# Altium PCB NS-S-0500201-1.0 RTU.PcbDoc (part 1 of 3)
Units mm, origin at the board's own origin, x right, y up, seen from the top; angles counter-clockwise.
Board outline 170 x 90 mm, 6 copper layers (TOP, L2_GND, L3_SIG, L4_VCC, L5_GND, BOT), stack 1.4 mm thick; 260 components, 230 nets, 1133 pads, 705 vias.
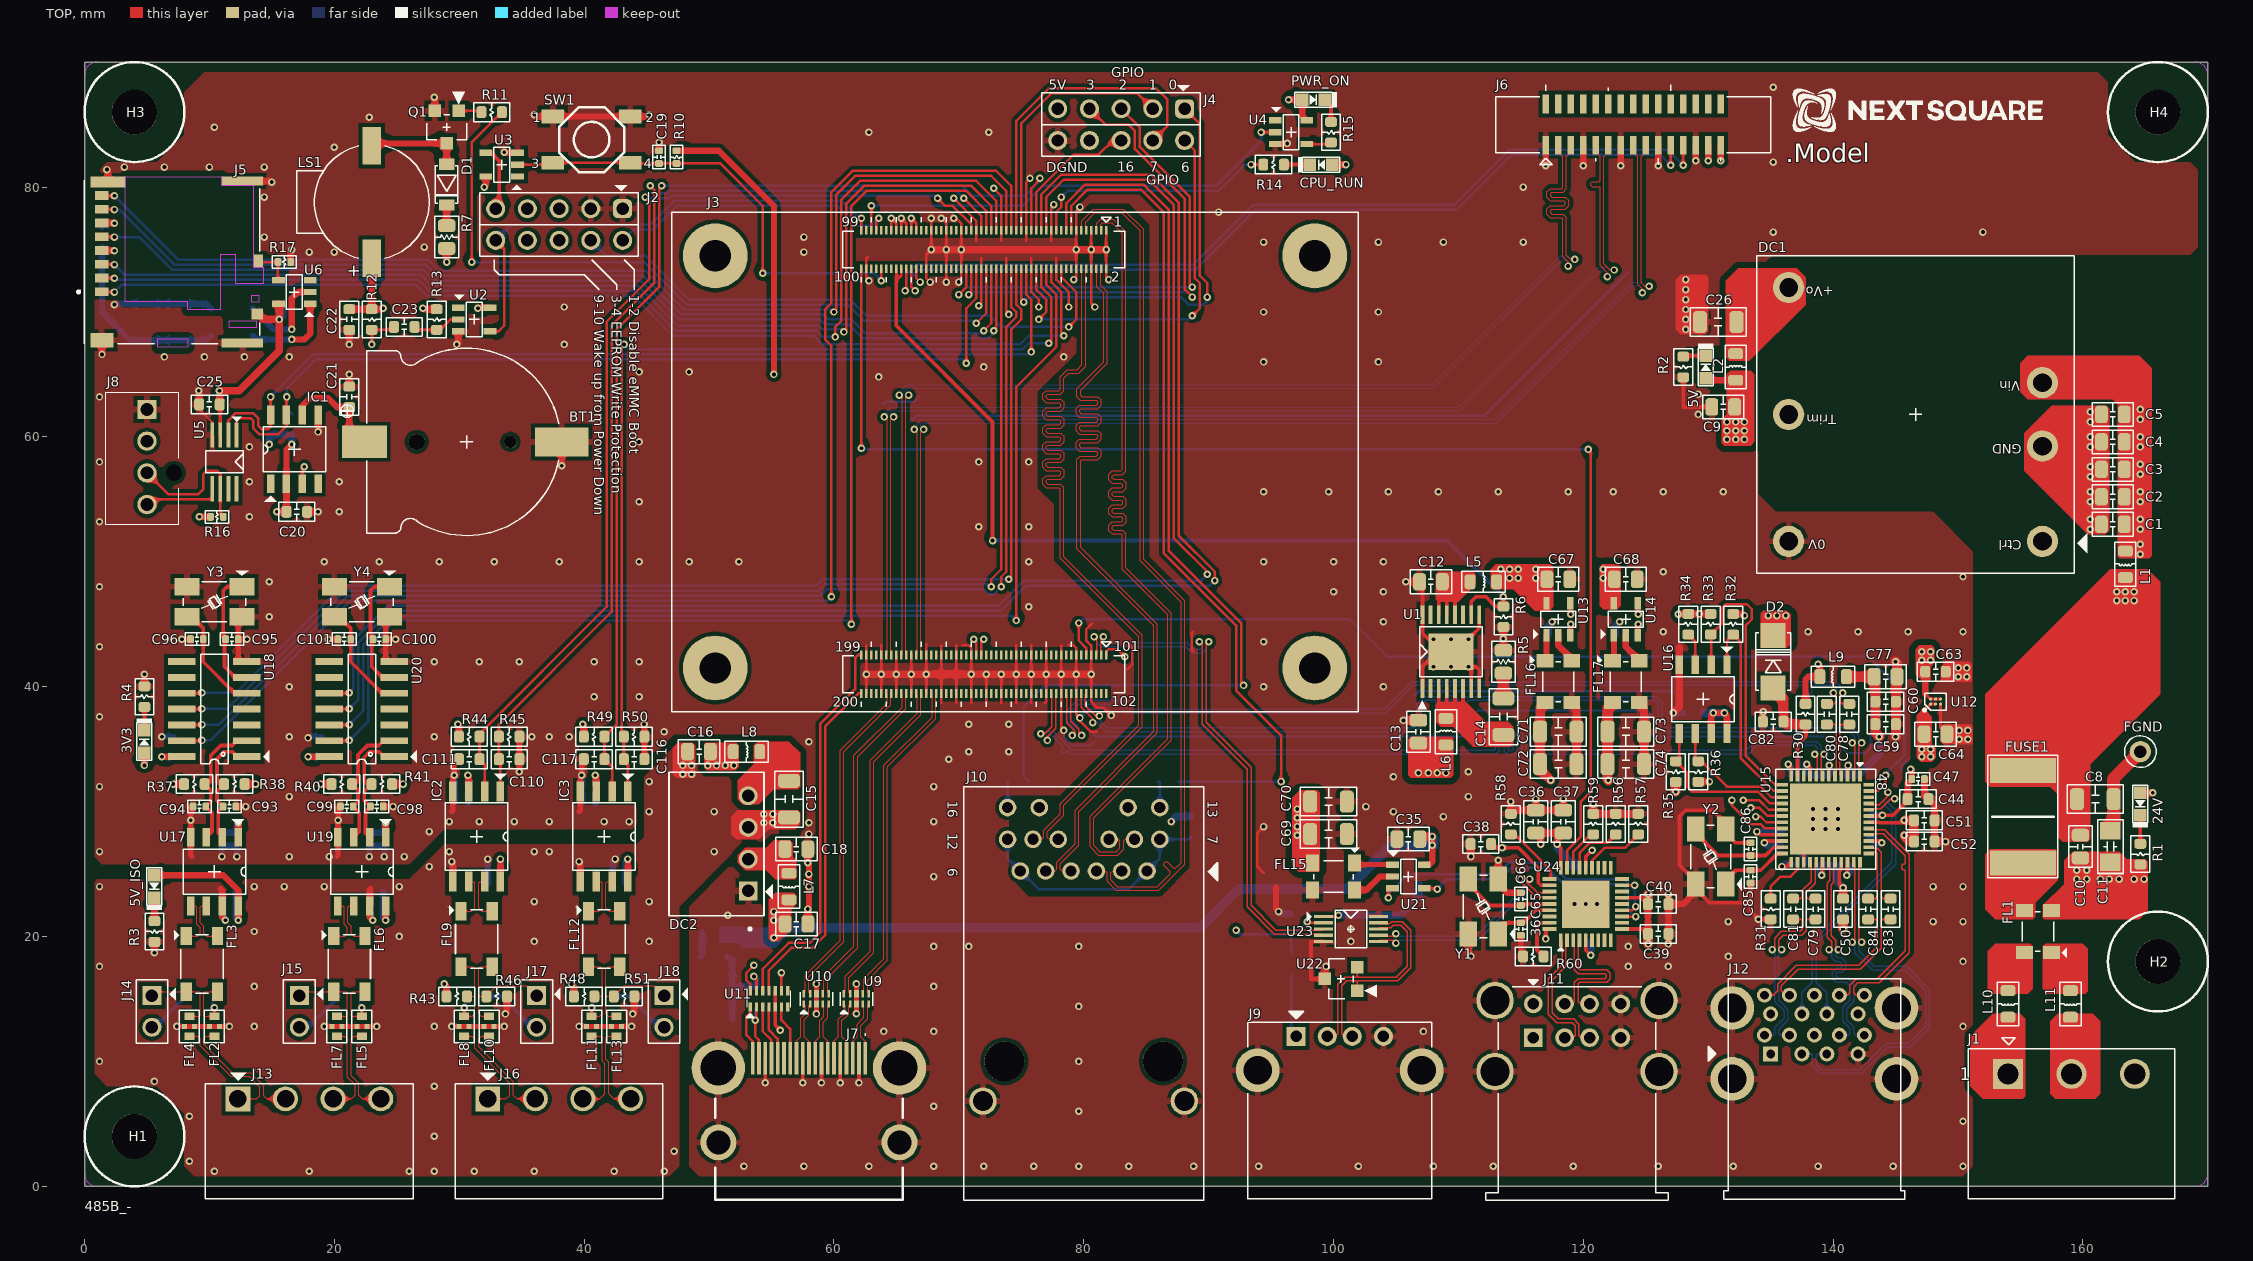
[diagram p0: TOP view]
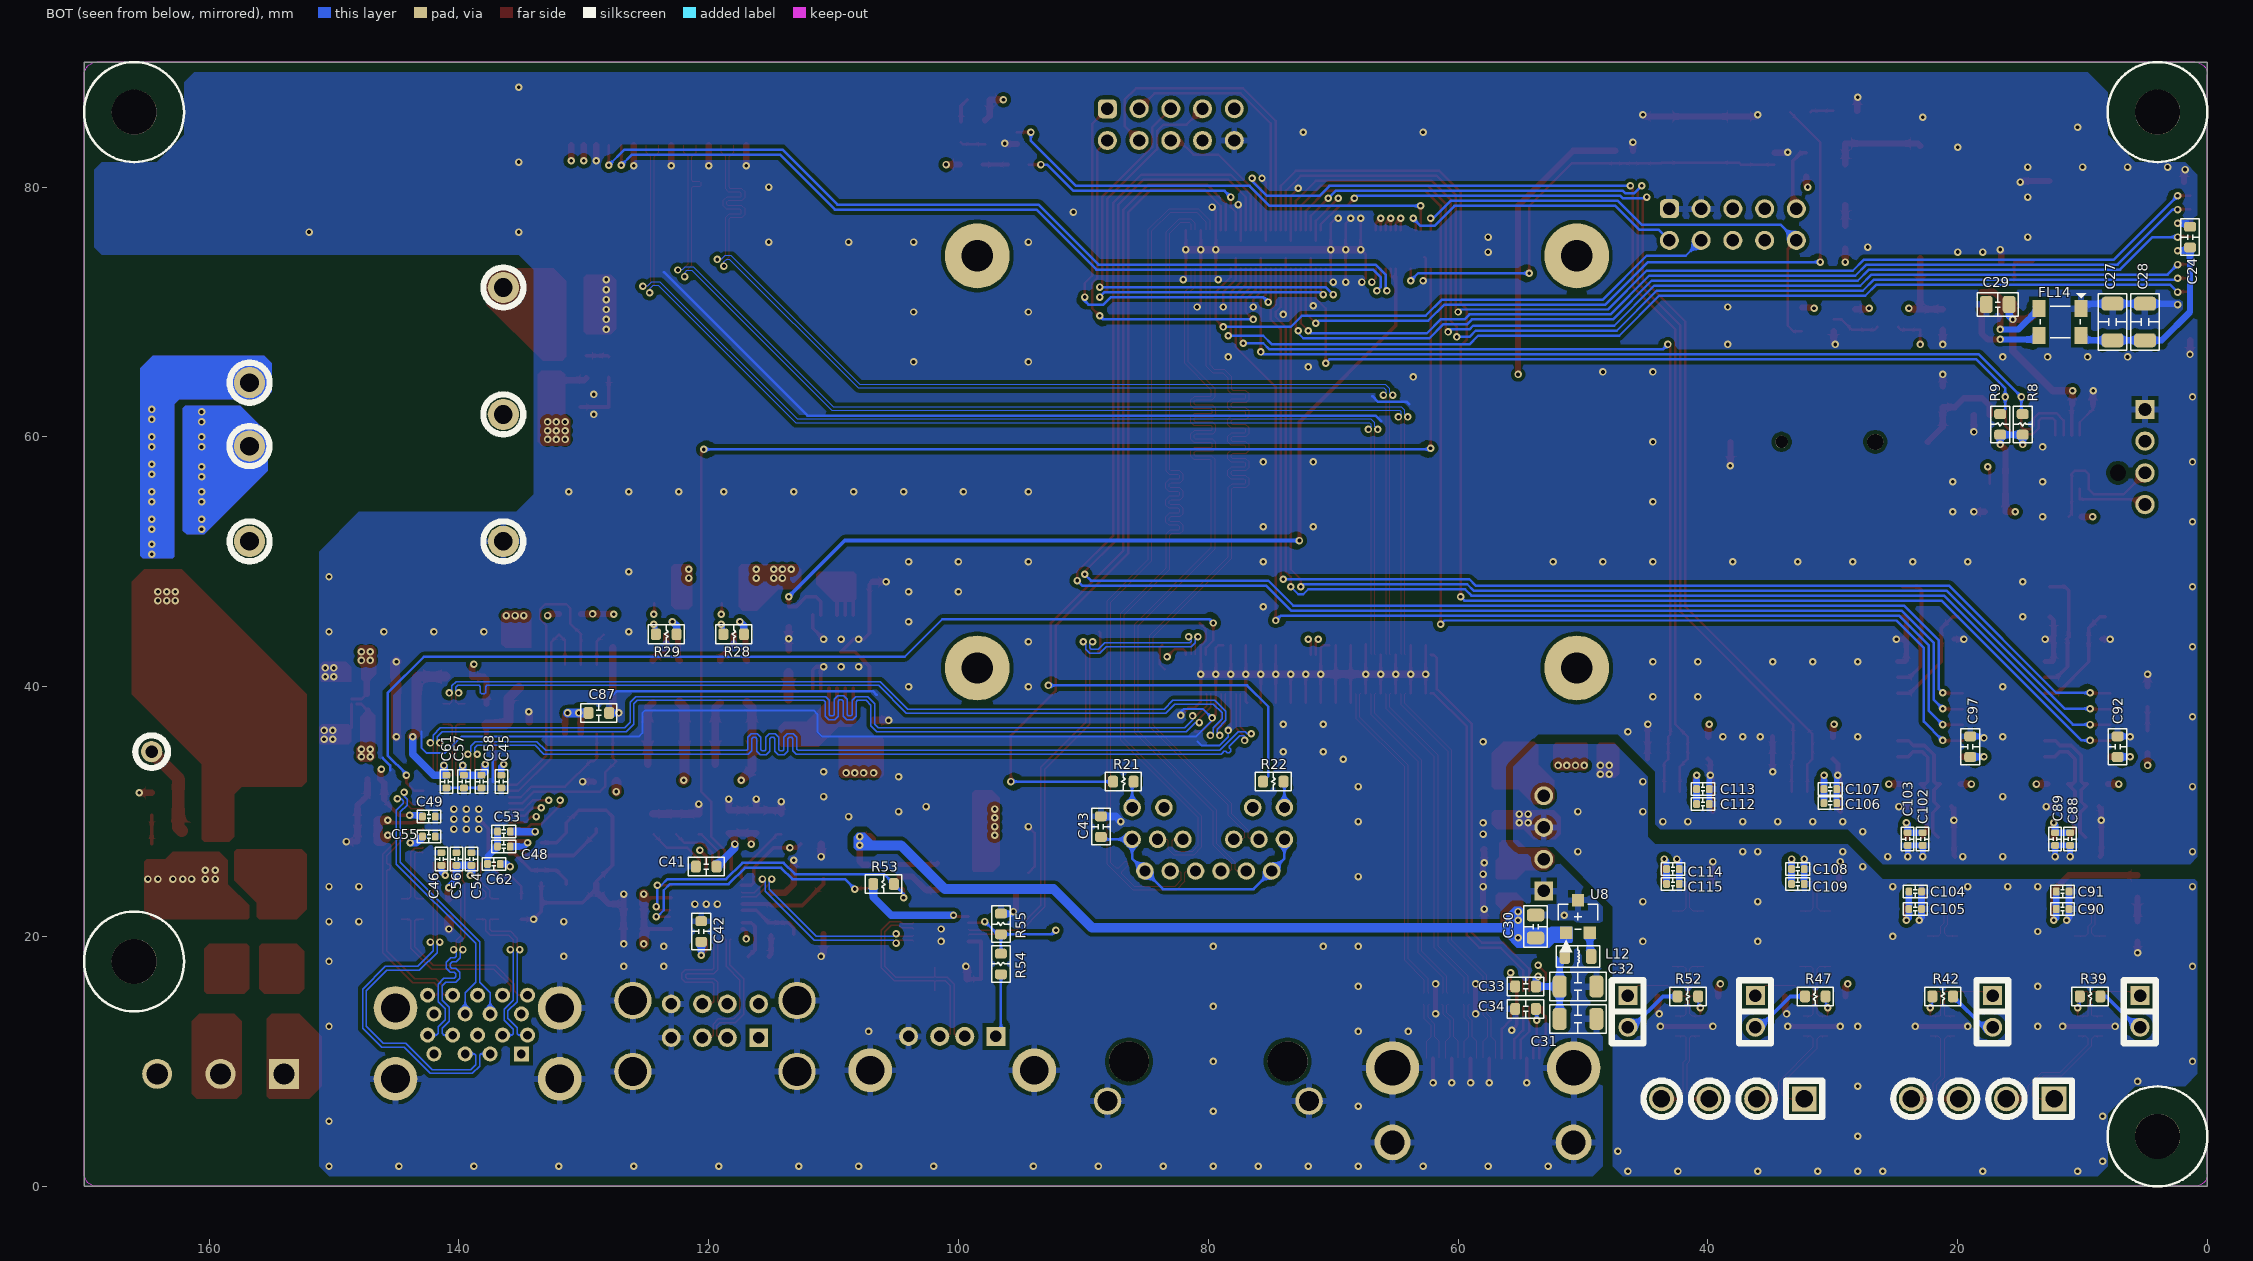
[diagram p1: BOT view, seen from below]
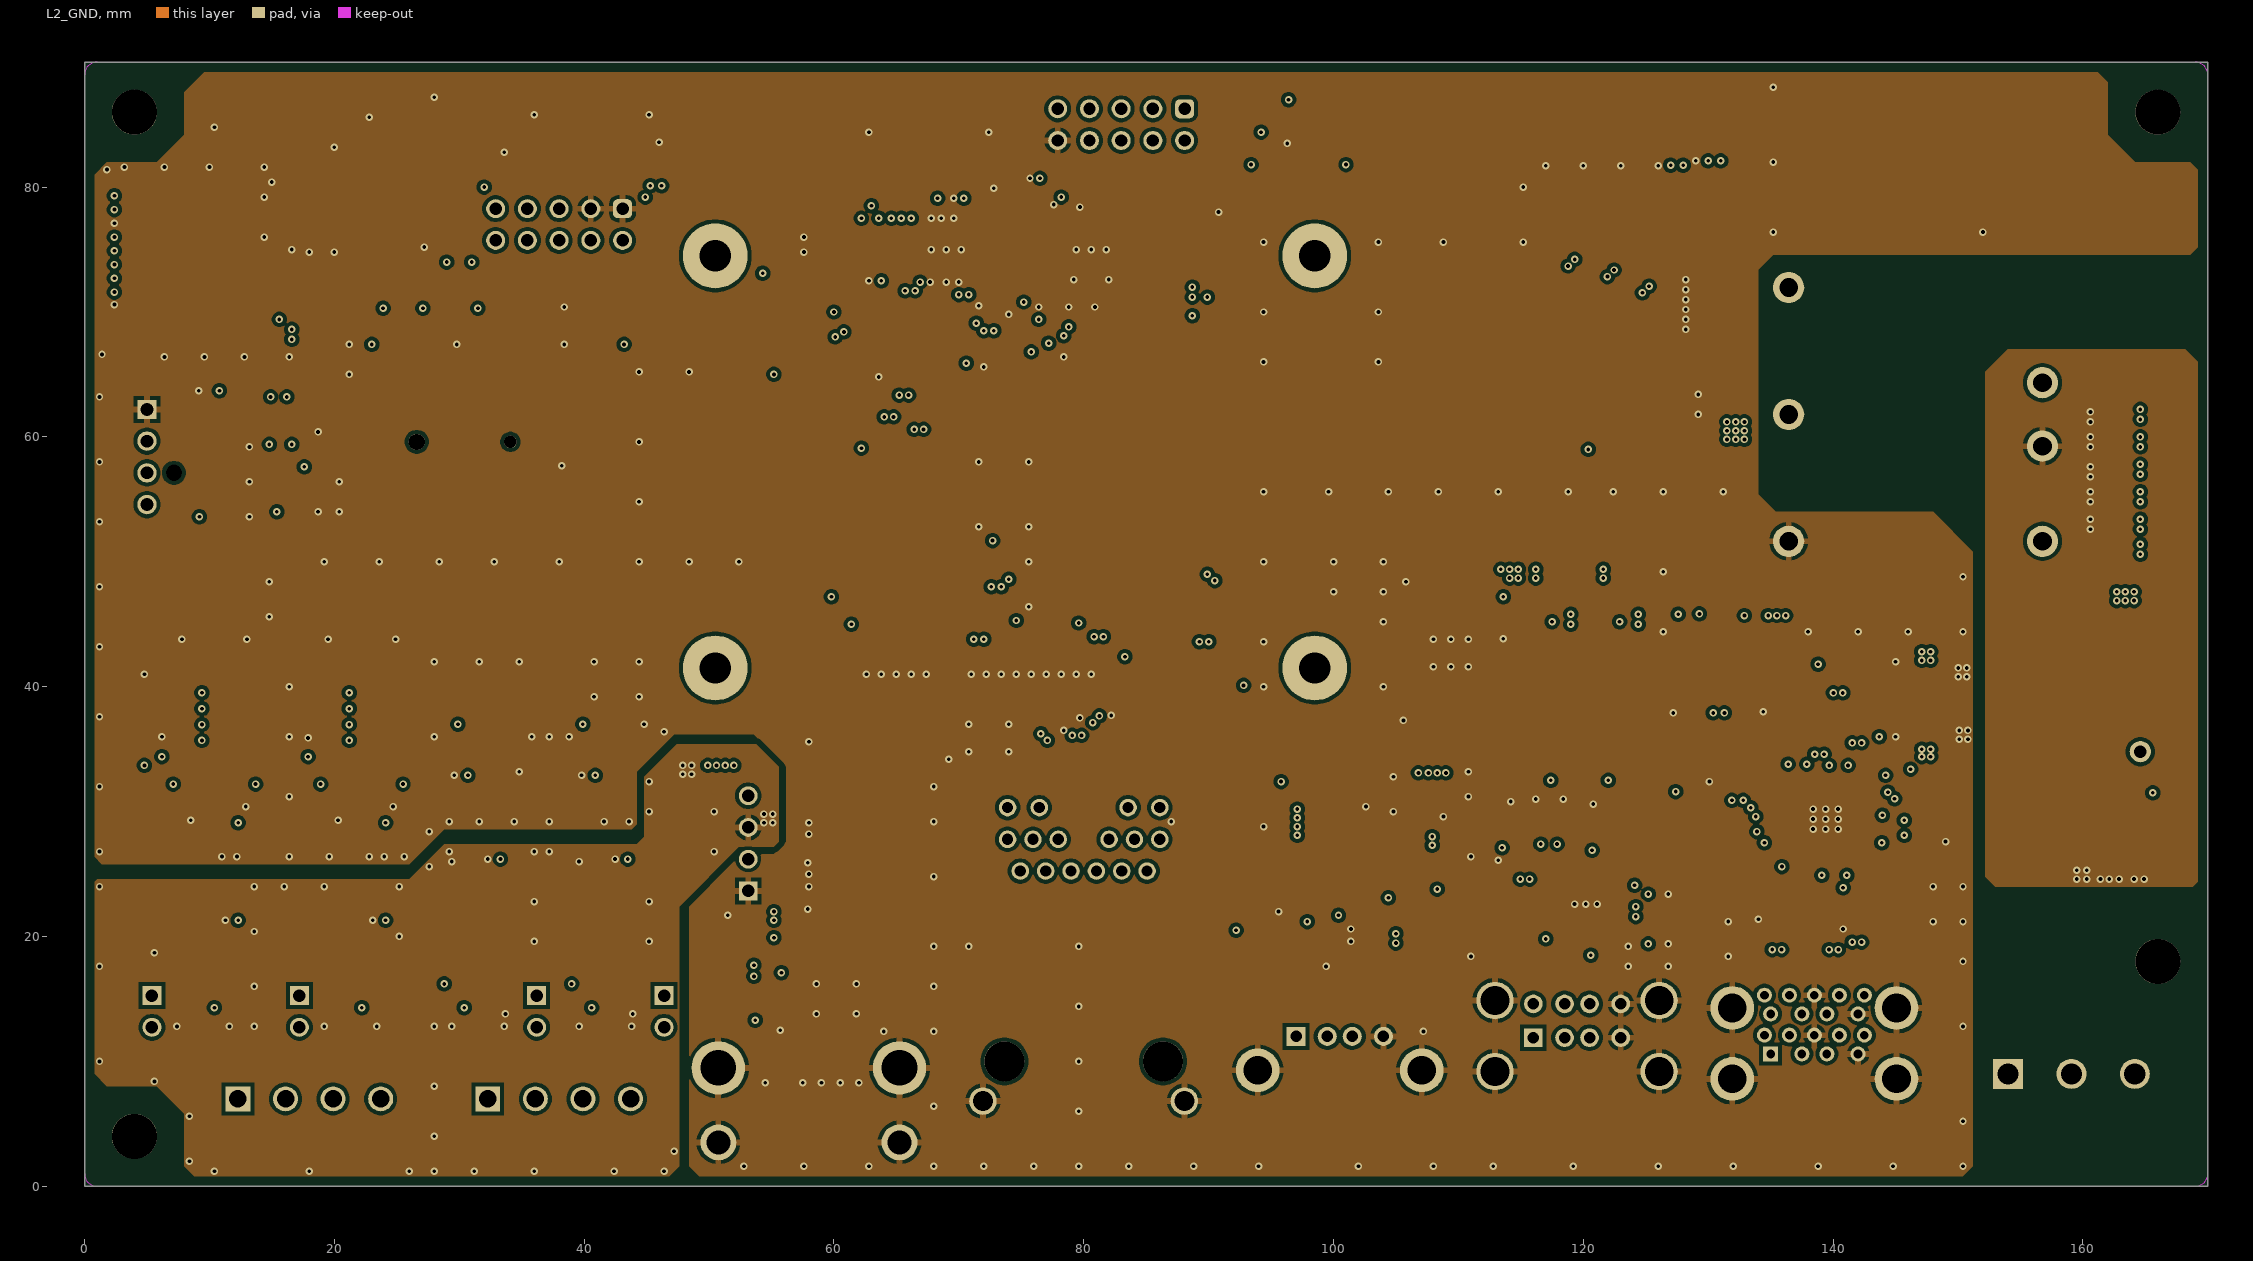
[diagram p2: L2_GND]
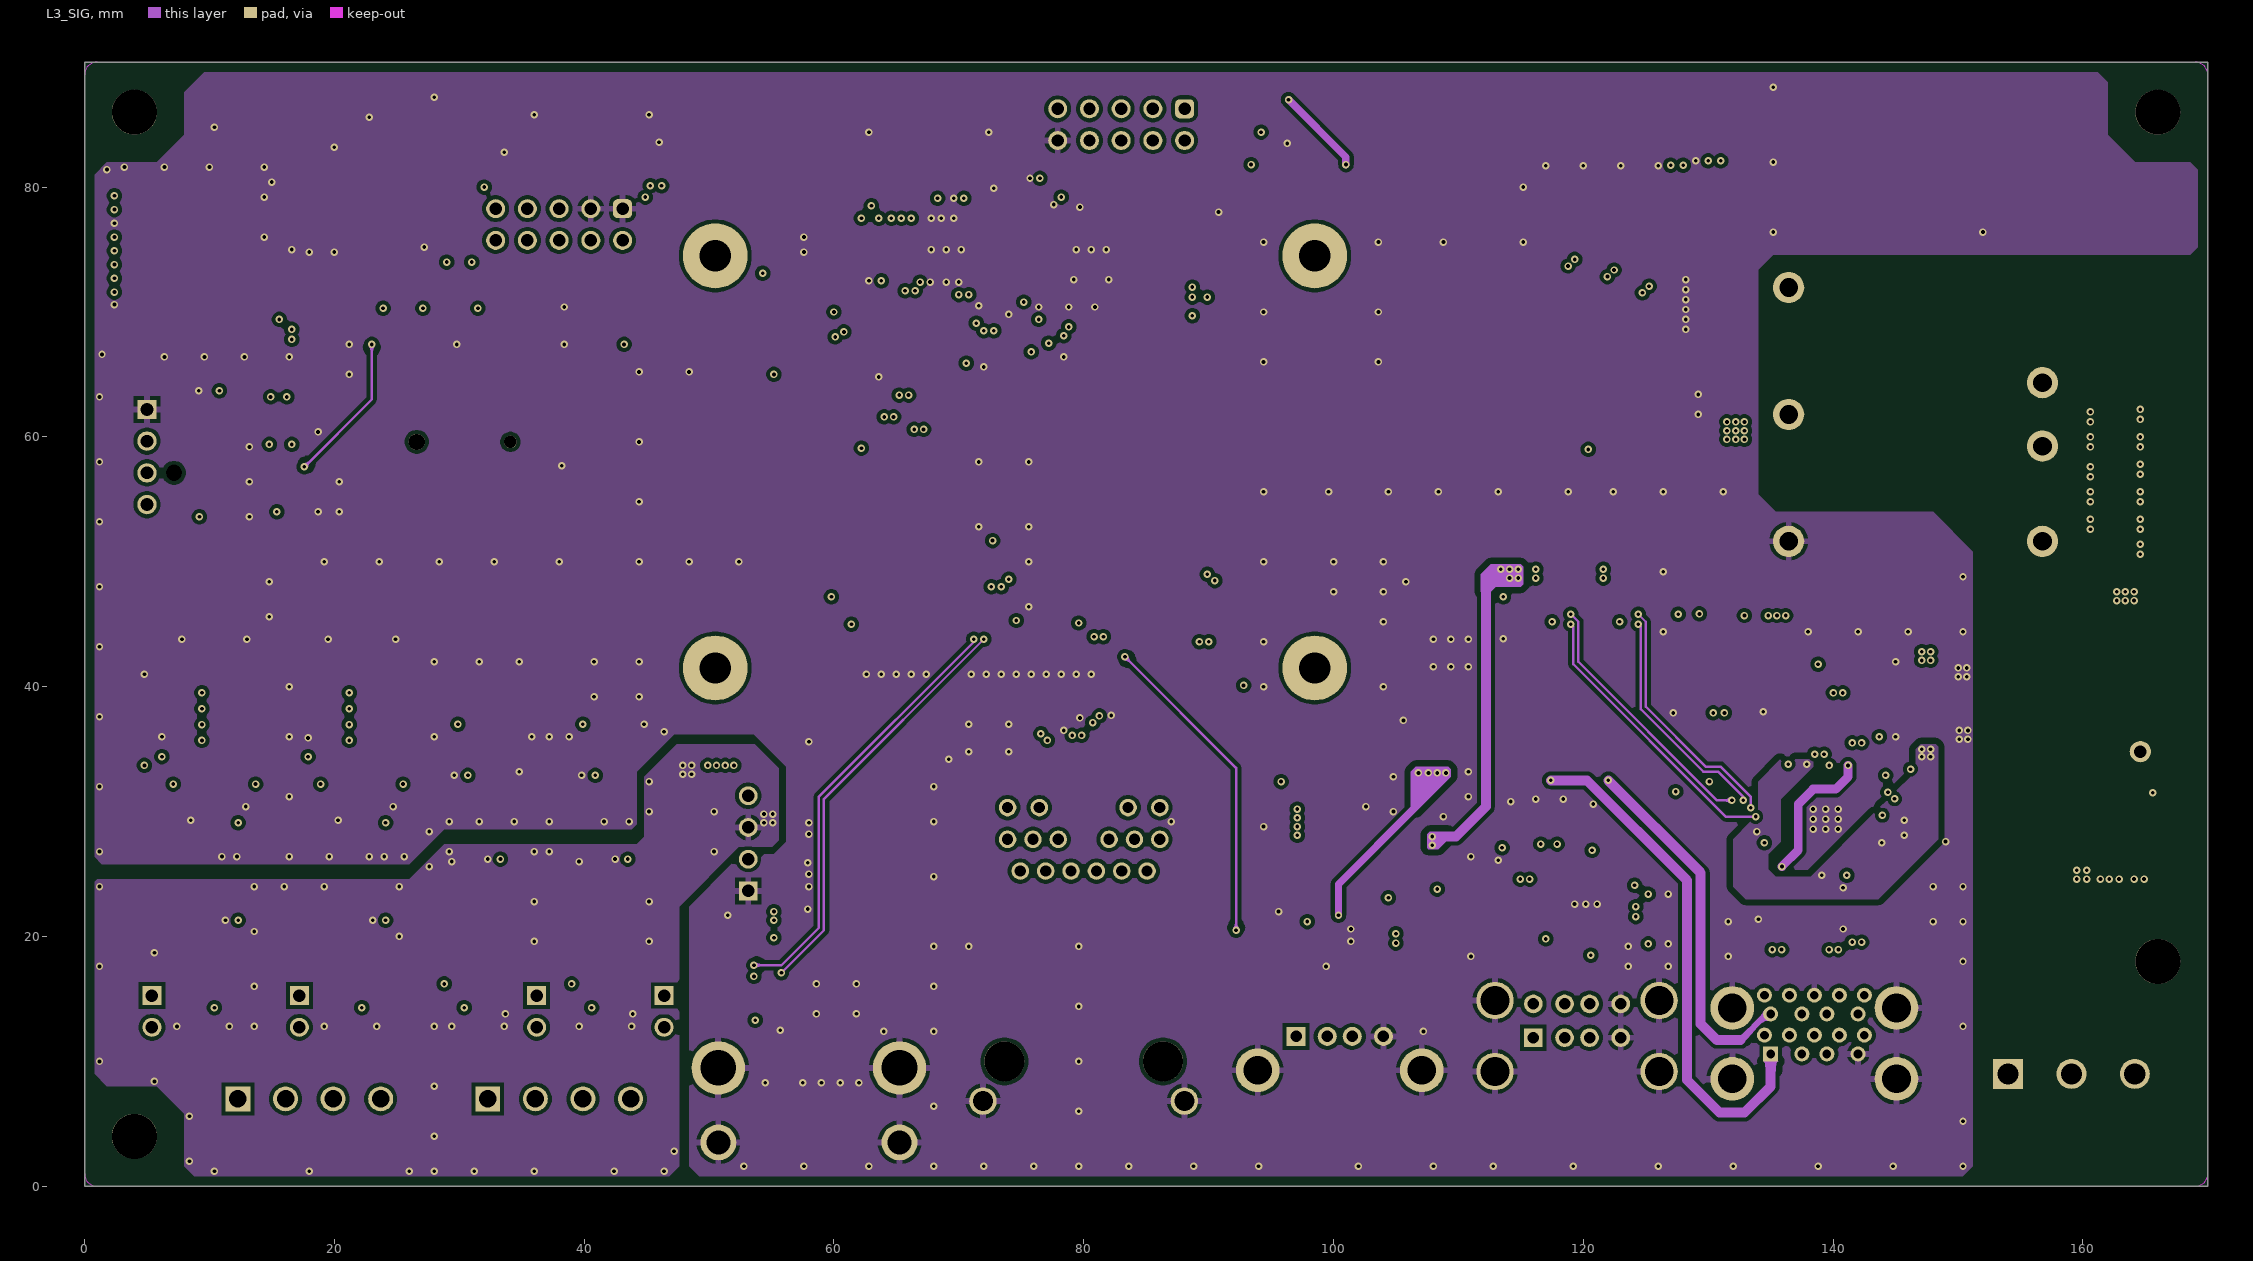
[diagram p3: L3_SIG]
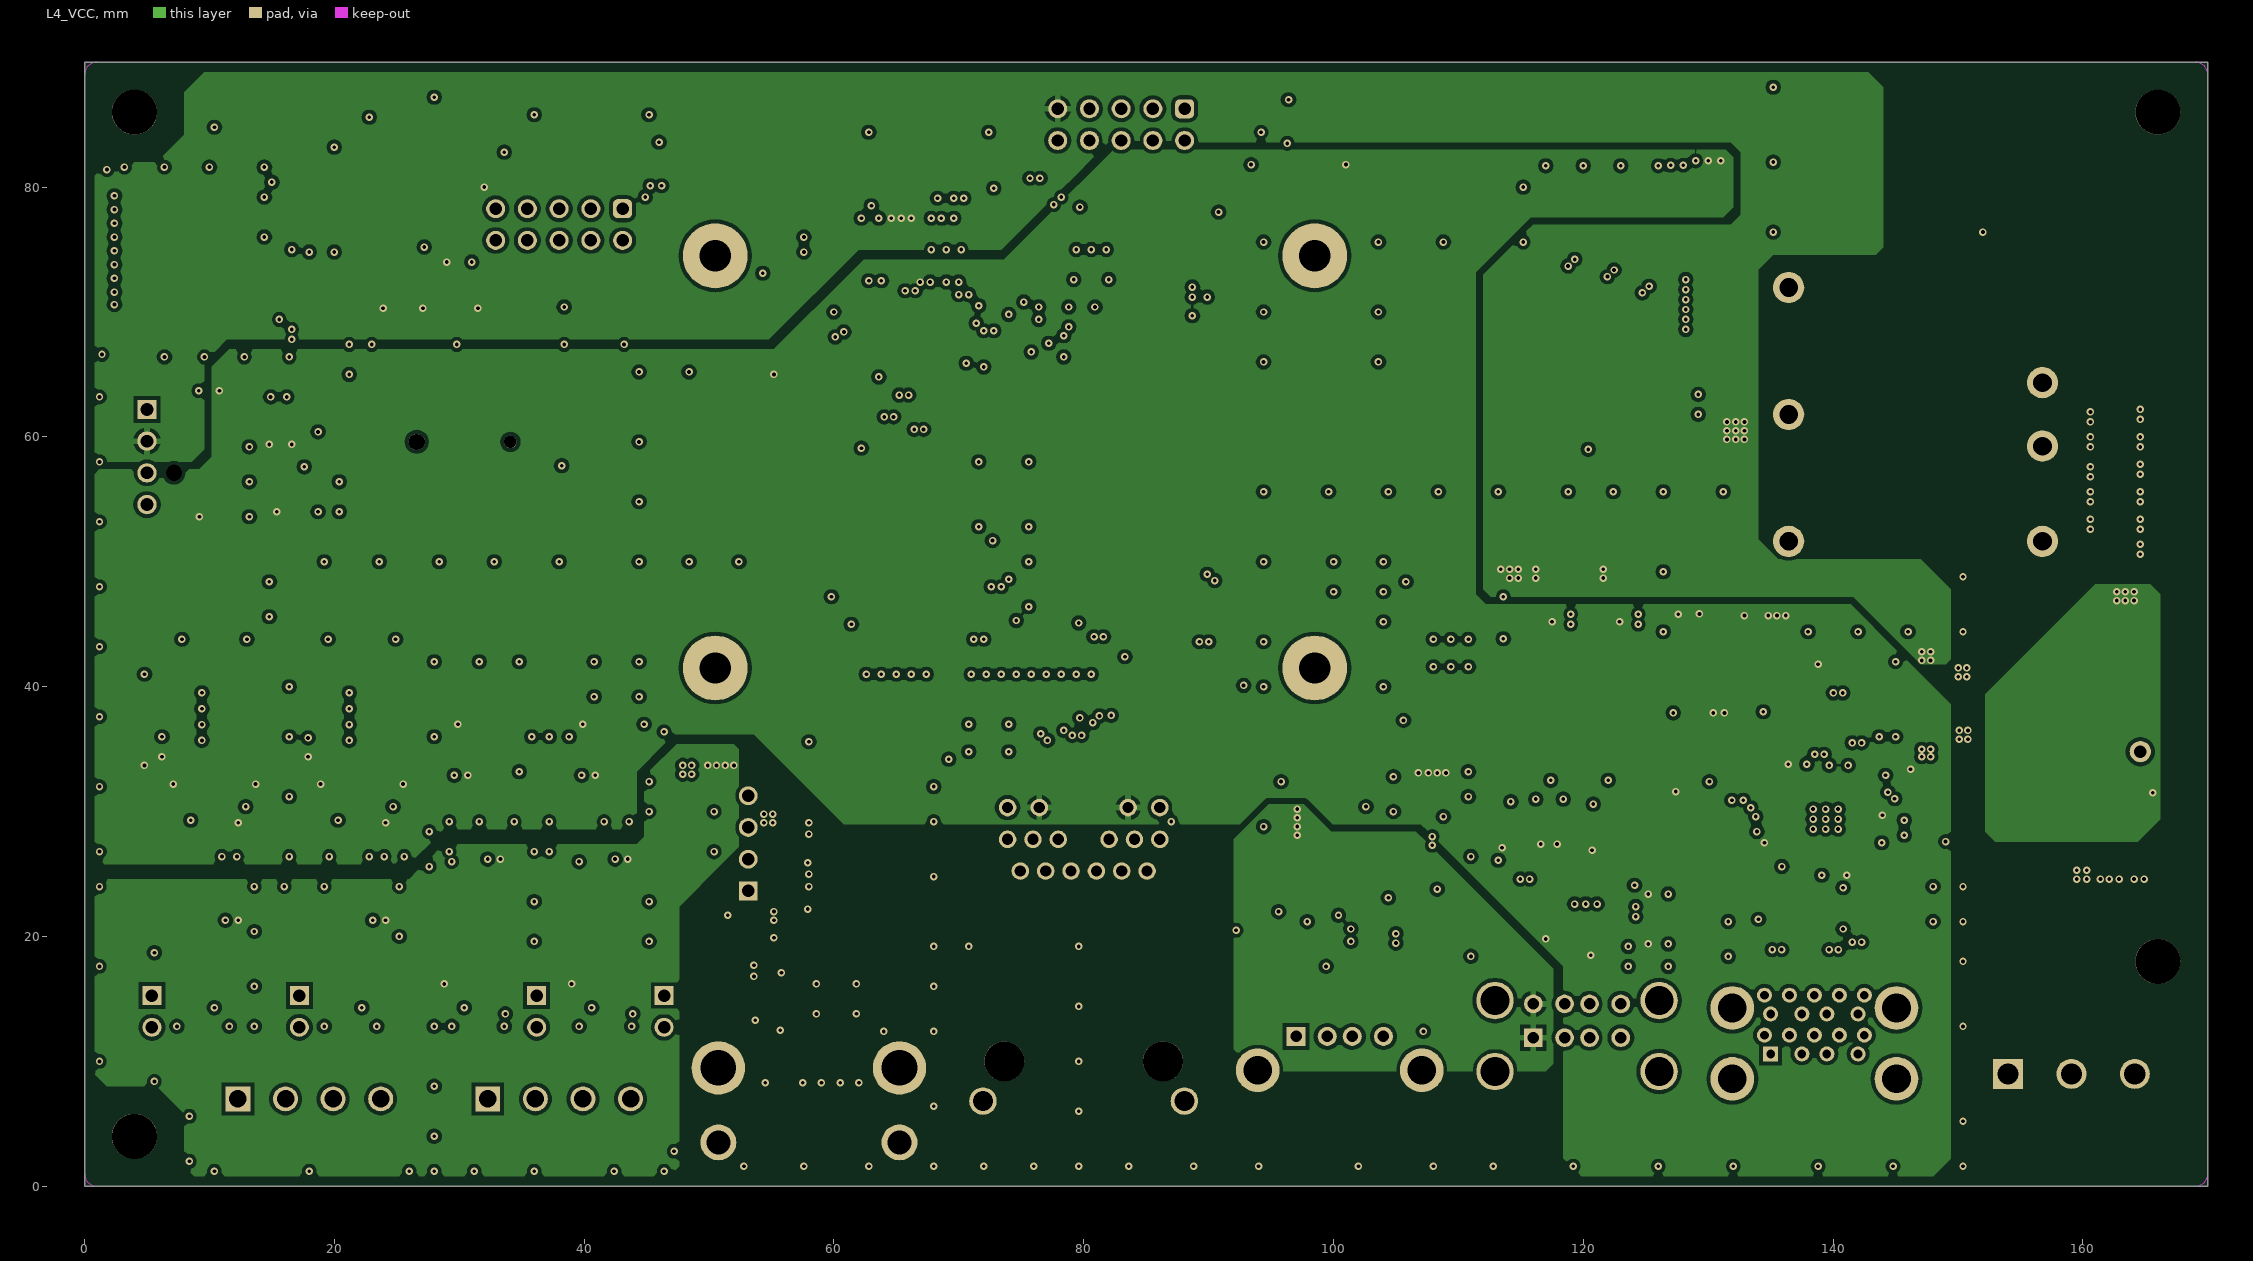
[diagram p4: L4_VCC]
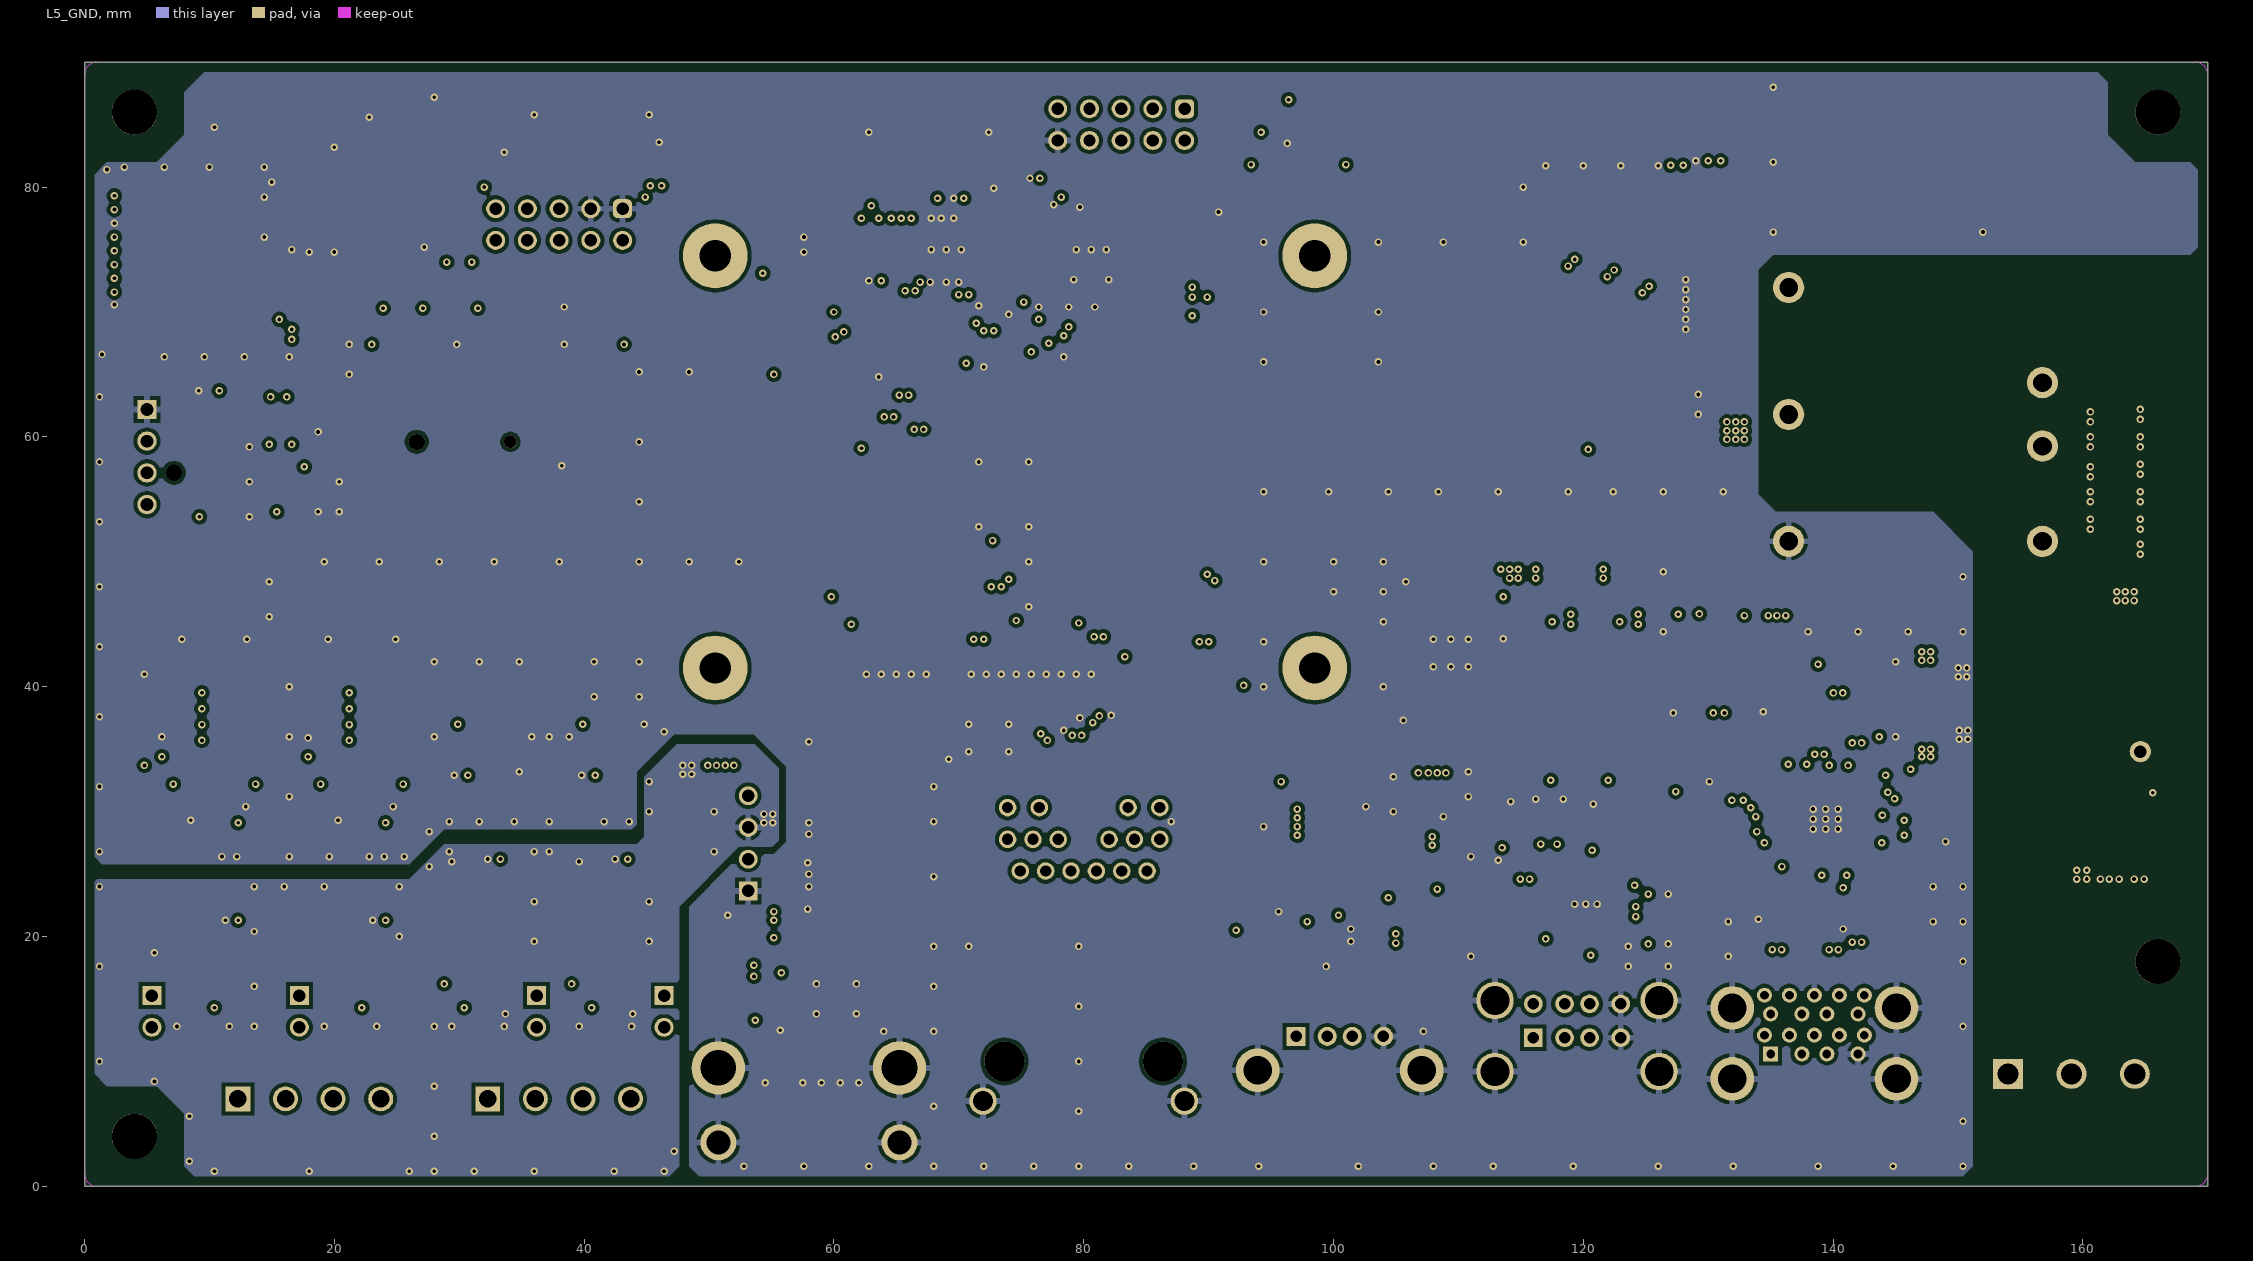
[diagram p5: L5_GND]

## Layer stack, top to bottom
Top Solder: solder mask 0.1, Solder Resist, Dk 3.5
TOP: signal copper 0.1
Dielectric1: core 0.1, FR-4, Dk 4.2
L2_GND: signal copper 0.1
Dielectric 1: prepreg 0.1, PP-006, Dk 4.2
L3_SIG: signal copper 0.1
Dielectric 4: prepreg 0.4, PP-006, Dk 4.1
L4_VCC: signal copper 0.1
Dielectric 3: prepreg 0.1, PP-006, Dk 4.1
L5_GND: signal copper 0.1
Dielectric 2: core 0.1, PP-006, Dk 4.2
BOT: signal copper 0.1
Bottom Solder: solder mask 0.1, Solder Resist, Dk 3.5

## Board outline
0,0 0,90 170,90 170,0

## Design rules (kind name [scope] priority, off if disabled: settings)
Clearance [All] p1: gap=0.15 ignorepadtopadclearanceinfootprint=FALSE except(0.3: Arc-Fill Arc-Poly Arc-Region Arc-Hole Track-Fill Track-Poly Track-Region Track-Hole SMDPad-Fill SMDPad-Poly SMDPad-Region SMDPad-Hole THPad-Fill THPad-Poly THPad-Region THPad-Hole Via-Fill Via-Poly Via-Region Via-Hole Fill-Hole Poly-Hole Region-Hole Text-Hole; 0.5: Fill-Fill Fill-Poly Fill-Region Poly-Poly Poly-Region Region-Region)
ComponentClearance [All] p1 off: gap=0.254 collisioncheckmode=3 verticalgap=0.254 showdistances=FALSE
DiffPairsRouting 100ohm [InDifferentialPairClass('100ohm')] p1: maxlimit=0.2 minlimit=0.2 mostfreqgap=0.2 toplayer_minwidth=0.09 toplayer_maxwidth=0.09 toplayer_prefwidth=0.09 midlayer1_minwidth=0.12 midlayer1_maxwidth=0.12 midlayer1_prefwidth=0.12 midlayer2_minwidth=0.09 midlayer2_maxwidth=0.09 midlayer2_prefwidth=0.09 midlayer3_minwidth=0.09 midlayer3_maxwidth=0.09 midlayer3_prefwidth=0.09 midlayer4_minwidth=0.09 midlayer4_maxwidth=0.09 midlayer4_prefwidth=0.09 bottomlayer_minwidth=0.09 bottomlayer_maxwidth=0.09 bottomlayer_prefwidth=0.09 maxuncoupledlength=12.7
DiffPairsRouting 90ohm [InDifferentialPairClass('90ohm')] p2: maxlimit=0.2 minlimit=0.2 mostfreqgap=0.2 toplayer_minwidth=0.11 toplayer_maxwidth=0.11 toplayer_prefwidth=0.11 midlayer1_minwidth=0.16 midlayer1_maxwidth=0.16 midlayer1_prefwidth=0.16 midlayer2_minwidth=0.11 midlayer2_maxwidth=0.11 midlayer2_prefwidth=0.11 midlayer3_minwidth=0.11 midlayer3_maxwidth=0.11 midlayer3_prefwidth=0.11 midlayer4_minwidth=0.11 midlayer4_maxwidth=0.11 midlayer4_prefwidth=0.11 bottomlayer_minwidth=0.11 bottomlayer_maxwidth=0.11 bottomlayer_prefwidth=0.11 maxuncoupledlength=12.7
FabricationTestPointUsage TestPointUsage [All] p1: valid=0 allowmultiple=FALSE
FabricationTestpoint Testpoint [All] p1: side=3 testpointundercomponent=TRUE minsize=1.016 maxsize=2.54 preferedsize=1.524 minholesize=0 maxholesize=1.016 preferedholesize=0.813 testpointgrid=0.025 allowsidetop=TRUE allowsidebottom=TRUE usegrid=TRUE gridtolerance=0
HoleSize [All] p1 off: absolutevalues=TRUE maxlimit=2.54 minlimit=0.025 maxpercent=80.000 minpercent=20.000
Length HDMI1 [InNetClass('HDMI1')] p1: maxlimit=2540 minlimit=0
Length PCI [InNetClass('PCI')] p2: maxlimit=79.5 minlimit=79.4
Length HDMI [InNetClass('HDMI')] p3: maxlimit=2540 minlimit=0
Length MIPI_DSI [InNetClass('MIPI')] p4: maxlimit=97 minlimit=96
Length Ethernet [InNetClass('Ethernet')] p5: maxlimit=68 minlimit=67.5
Length USB3_0 [InNetClass('USB3_0')] p6: maxlimit=2540 minlimit=0
Length USB2_0 [InNetClass('USB2_0')] p7: maxlimit=11 minlimit=10
PlaneClearance [All] p1: clearance=0.2
PlaneConnect [All] p1: planeconnectstyle=Direct reliefexpansion=0.17 reliefentries=4 reliefconductorwidth=0.254 reliefairgap=0.17
PolygonConnect PolygonConnect_1 [All vs IsPad] p1: connectstyle=Relief reliefconductorwidth=0.5 reliefentries=4 polygonreliefangle="90 Angle" airgapwidth=0.3
PolygonConnect [All] p2: connectstyle=Direct reliefconductorwidth=0.254 reliefentries=4 polygonreliefangle="45 Angle" airgapwidth=0.254
RoutingVias [All] p1: holewidth=0.3 width=0.6 viastyle="Through Hole" minholewidth=0.2 minwidth=0.4 maxholewidth=0.5 maxwidth=1
SilkToSolderMaskClearance SilkscreenOverComponentPads [IsPad] p1: minsilkscreentomaskgap=0.254 clearancetoexposedcopper=TRUE
SolderMaskExpansion [All] p1: expansion=0 istentingtop=FALSE
Width [All] p1: maxlimit=5 minlimit=0.1 preferedwidth=0.2
22 further rules are at their usual default settings.

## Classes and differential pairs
net class HDMI1: HDMI0_CLK1_N HDMI0_CLK1_P HDMI0_TX01_N HDMI0_TX01_P HDMI0_TX11_N HDMI0_TX11_P HDMI0_TX21_N HDMI0_TX21_P
component class 10_HW_Component: J19 J20 J21 Pin1 Pin2 Pin3 Pin4 T1
component class 6_USB2.0: C35 C36 C37 C38 C39 C40 C41 C42 C65 C66 C69 C70 FL15 J9 J11 R53 R54 R55 R56 R57 R58 R59 R60 U21 U22 U23 U24 Y1
net class USB3_0: U3RXD1_N U3RXD1_P U3RXD2_N U3RXD2_P U3TXD1_1_N U3TXD1_1_P U3TXD1_N U3TXD1_P U3TXD2_1_N U3TXD2_1_P U3TXD2_N U3TXD2_P
net class USB2_0: USB_DN1_N USB_DN1_P USB_DN2_N USB_DN2_P
net class PCI: PCIe_CLK_N PCIe_CLK_P PCIe_TX_N PCIe_TX_P
net class MIPI_DSI: DSI1_C_N DSI1_C_P DSI1_D0_N DSI1_D0_P DSI1_D1_N DSI1_D1_P
net class HDMI: HDMI0_CLK_N HDMI0_CLK_P HDMI0_TX0_N HDMI0_TX0_P HDMI0_TX1_N HDMI0_TX1_P HDMI0_TX2_N HDMI0_TX2_P
net class Ethernet: Ethernet_Pair0_N Ethernet_Pair0_P Ethernet_Pair1_N Ethernet_Pair1_P Ethernet_Pair2_N Ethernet_Pair2_P Ethernet_Pair3_N Ethernet_Pair3_P
differential pair class 100ohm: 485A 485A1 485A2 485B 485B1 485B2 CANA CANA1 CANA2 CANB CANB1 CANB2 DSI1_C DSI1_D0 DSI1_D1 Ethernet_Pair0 Ethernet_Pair1 Ethernet_Pair2 Ethernet_Pair3 HDMI0_CLK HDMI0_CLK1 HDMI0_TX0 HDMI0_TX01 HDMI0_TX1 HDMI0_TX2 HDMI0_TX11 HDMI0_TX21
differential pair class 90ohm: PCIe_CLK PCIe_RX PCIe_RX1 PCIe_TX U2D1 U2D2 U3RXD1 U3RXD2 U3TXD1 U3TXD1_1 U3TXD2 U3TXD2_1 USB USB_DN1 USB_DN2 USB_HSD USB_HSD1
component class 9_RS485: C106 C107 C108 C109 C110 C111 C112 C113 C114 C115 C116 C117 FL8 FL9 FL10 FL11 FL12 FL13 IC2 IC3 J16 J17 J18 R43 R44 R45 R46 R47 R48 R49 R50 R51 R52
component class 7_USB3.0: C44 C45 C46 C47 C48 C49 C50 C51 C52 C53 C54 C55 C56 C57 C58 C59 C60 C61 C62 C63 C64 C67 C68 C71 C72 C73 C74 C77 C78 C79 C80 C81 C82 C83 C84 C85 C86 C87 D2 FL16 FL17 J12 L9 R28 R29 R30 R31 R32 R33 R34 R35 R36 U12 U13 U14 U15 U16 Y2
component class 5_PERIPHERALS: C24 C25 C27 C28 C29 C30 C31 C32 C33 C34 C43 FL14 J5 J6 J7 J8 J10 L12 R16 R17 R21 R22 U5 U6 U8 U9 U10 U11
component class 4_CM4_CONN: CPU_RUN J3 J4 PWR_ON R14 R15 U4
component class 3_Power_Boot: 3V3 5V 5V_ISO 24V BT1 C1 C2 C3 C4 C5 C8 C9 C10 C11 C12 C13 C14 C15 C16 C17 C18 C19 C20 C21 C22 C23 C26 D1 DC1 DC2 FGND FL1 FUSE1 H1 H2 H3 H4 IC1 J1 J2 L1 L2 L5 L6 L7 L8 L10 L11 LS1 Q1 R1 R2 R3 R4 R5 R6 R7 R8 R9 R10 R11 R12 R13 SW1 U1 U2 U3
component class 8_CANFD: C88 C89 C90 C91 C92 C93 C94 C95 C96 C97 C98 C99 C100 C101 C102 C103 C104 C105 FL2 FL3 FL4 FL5 FL6 FL7 J13 J14 J15 R37 R38 R39 R40 R41 R42 U17 U18 U19 U20 Y3 Y4
differential pair HDMI0_TX21: +HDMI0_TX21_P -HDMI0_TX21_N
differential pair HDMI0_TX11: +HDMI0_TX11_P -HDMI0_TX11_N
differential pair HDMI0_TX01: +HDMI0_TX01_P -HDMI0_TX01_N
differential pair HDMI0_CLK1: +HDMI0_CLK1_P -HDMI0_CLK1_N
differential pair U3TXD2_1: +U3TXD2_1_P -U3TXD2_1_N
differential pair U3TXD1_1: +U3TXD1_1_P -U3TXD1_1_N
differential pair PCIe_RX1: +PCIe_RX1_P -PCIe_RX1_N
differential pair CANB2: +CANB2_P -CANB2_N
differential pair CANB1: +CANB1_P -CANB1_N
differential pair CANA2: +CANA2_P -CANA2_N
differential pair CANA1: +CANA1_P -CANA1_N
differential pair 485B2: +485B2_P -485B2_N
differential pair 485B1: +485B1_P -485B1_N
differential pair 485A2: +485A2_P -485A2_N
differential pair 485A1: +485A1_P -485A1_N
differential pair U2D2: +U2D2_P -U2D2_N
differential pair U2D1: +U2D1_P -U2D1_N
differential pair USB_HSD1: +USB_HSD1_P -USB_HSD1_N
differential pair USB_DN2: +USB_DN2_P -USB_DN2_N
differential pair USB_DN1: +USB_DN1_P -USB_DN1_N
differential pair USB_HSD: +USB_HSD_P -USB_HSD_N
differential pair U3TXD2: +U3TXD2_P -U3TXD2_N
differential pair U3TXD1: +U3TXD1_P -U3TXD1_N
differential pair U3RXD2: +U3RXD2_P -U3RXD2_N
differential pair U3RXD1: +U3RXD1_P -U3RXD1_N
differential pair USB: +USB_P -USB_N
differential pair HDMI0_TX2: +HDMI0_TX2_P -HDMI0_TX2_N
differential pair HDMI0_TX1: +HDMI0_TX1_P -HDMI0_TX1_N
differential pair HDMI0_TX0: +HDMI0_TX0_P -HDMI0_TX0_N
differential pair HDMI0_CLK: +HDMI0_CLK_P -HDMI0_CLK_N
differential pair DSI1_D1: +DSI1_D1_P -DSI1_D1_N
differential pair DSI1_D0: +DSI1_D0_P -DSI1_D0_N
differential pair DSI1_C: +DSI1_C_P -DSI1_C_N
differential pair PCIe_TX: +PCIe_TX_P -PCIe_TX_N
differential pair PCIe_RX: +PCIe_RX_P -PCIe_RX_N
differential pair PCIe_CLK: +PCIe_CLK_P -PCIe_CLK_N
differential pair Ethernet_Pair3: +Ethernet_Pair3_P -Ethernet_Pair3_N
differential pair Ethernet_Pair2: +Ethernet_Pair2_P -Ethernet_Pair2_N
differential pair Ethernet_Pair1: +Ethernet_Pair1_P -Ethernet_Pair1_N
differential pair Ethernet_Pair0: +Ethernet_Pair0_P -Ethernet_Pair0_N
differential pair CANB: +CANB_P -CANB_N
differential pair CANA: +CANA_P -CANA_N
differential pair 485B: +485B_P -485B_N
differential pair 485A: +485A_P -485A_N

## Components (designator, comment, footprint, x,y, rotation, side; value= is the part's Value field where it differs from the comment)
3V3 "LED Green[1608]" LED1608 4.8,35.6 r90 top value=GREEN
5V "LED Green[1608]" LED1608 129.8,65.6 r90 top value=GREEN
5V_ISO "LED Green[1608]" LED1608 5.6,24 r270 top value=GREEN
24V "LED Green[1608]" LED1608 164.6,30.6 r270 top value=GREEN
BT1 "CH291-1220LF" CH291-1220LF 30.6,59.6 r180 top value=-
C1 "C [2012]" C2012 162.4,53 r180 top value=22uF/35V/2012/M
C2 "C [2012]" C2012 162.4,55.2 r180 top value=22uF/35V/2012/M
C3 "C [2012]" C2012 162.4,57.4 r180 top value=22uF/35V/2012/M
C4 "C [2012]" C2012 162.4,59.6 r180 top value=22uF/35V/2012/M
C5 "C [2012]" C2012 162.4,61.8 r180 top value=22uF/35V/2012/M
C8 "202R18W102KV4E" C3216#1 161,31 r180 top value=2000V/1000pF
C9 "C [2012]" C2012 131.2,62.4 r0 top value=10uF/50V/2012/K
C10 "C [2012]" C2012 159.8,27.2 r270 top value=10uF/50V/2012/K
C11 "202R18W102KV4E" C3216#2 162.2,27.2 r90 top value=2000V/1000pF
C12 "C [2012]" C2012 107.8,48.4 r180 top value=10uF/50V/2012/K
C13 "C [2012]" C2012 106.8,36.4 r90 top value=10uF/50V/2012/K
C14 "C [3216]" C3216#1 113.6,37.6 r90 top value=100uF/10V/3216/K
C15 "C [3216]" C3216#1 56.4,31 r270 top value=100uF/10V/3216/K
C16 "C [2012]" C2012 49.2,34.8 r0 top value=10uF/50V/2012/K
C17 "C [2012]" C2012 57,21 r180 top value=10uF/50V/2012/K
C18 "C [2012]" C2012 57,27 r180 top value=10uF/50V/2012/K
C19 "C [1005]" C1005 46,82.4 r90 top value=0.1uF/50V/1005/K
C20 "C [1608]" C1608 17,54 r0 top value=0.1uF/50V/1608/K
C21 "C [1608]" C1608 21.2,63.2 r90 top value=0.1uF/50V/1608/K
C22 "C [1608]" C1608 21.2,69.4 r270 top value=0.1uF/50V/1608/K
C23 "C [1608]" C1608 25.6,68.8 r0 top value=0.1uF/50V/1608/K
C24 "C [1608]" C1608 1.4,76 r90 bottom value=0.1uF/50V/1608/K
C25 "C [1608]" C1608 10,62.6 r180 top value=0.1uF/50V/1608/K
C26 "C [3216]" C3216#1 130.8,69.2 r180 top value=100uF/10V/3216/K
C27 "C [3216]" C3216#1 7.6,69.2 r270 bottom value=100uF/10V/3216/K
C28 "C [3216]" C3216#1 5,69.2 r270 bottom value=47uF/16V/3216/M
C29 "C [2012]" C2012 16.8,70.6 r180 bottom value=10uF/50V/2012/K
C30 "C [2012]" C2012 53.8,20.8 r270 bottom value=10uF/50V/2012/K
C31 "C [3216]" C3216#1 50.4,13.4 r0 bottom value=100uF/10V/3216/K
C32 "C [3216]" C3216#1 50.4,16 r0 bottom value=47uF/16V/3216/M
C33 "C [1608]" C1608 54.6,16 r0 bottom value=0.1uF/50V/1608/K
C34 "C [1608]" C1608 54.6,14.2 r0 bottom value=0.1uF/50V/1608/K
C35 "C [2012]" C2012 106,27.8 r0 top value=10uF/50V/2012/K
C36 "C [2012]" C2012 116.2,29.2 r270 top value=10uF/50V/2012/K
C37 "C [2012]" C2012 118.4,29.2 r270 top value=10uF/50V/2012/K
C38 "C [1608]" C1608 111.8,27.4 r180 top value=0.1uF/50V/1608/K
C39 "C [1608]" C1608 126,20.2 r0 top value=0.1uF/50V/1608/K
C40 "C [1608]" C1608 126,22.6 r0 top value=0.1uF/50V/1608/K
C41 "C [1608]" C1608 120.2,25.6 r0 bottom value=0.1uF/50V/1608/K
C42 "C [1608]" C1608 120.6,20.4 r90 bottom value=0.1uF/50V/1608/K
C43 "C [1608]" C1608 88.6,28.8 r90 bottom value=0.1uF/50V/1608/K
C44 "C [1608]" C1608 146.8,31 r0 top value=0.1uF/50V/1608/K
C45 "C [1005]" C1005 136.6,32.4 r270 bottom value=10nF/50V/1005/K
C46 "C [1005]" C1005 141.4,26.2 r90 bottom value=10nF/50V/1005/K
C47 "C [1005]" C1005 146.8,32.6 r0 top value=10nF/50V/1005/K
C48 "C [1005]" C1005 136.4,27.2 r0 bottom value=10nF/50V/1005/K
C49 "C [1005]" C1005 142.4,29.6 r180 bottom value=10nF/50V/1005/K
C50 "C [1608]" C1608 140.8,22.2 r270 top value=0.1uF/50V/1608/K
C51 "C [1608]" C1608 147.3,29.3 r0 top value=0.1uF/50V/1608/K
C52 "C [1608]" C1608 147.3,27.6 r0 top value=0.1uF/50V/1608/K
C53 "C [1005]" C1005 136.4,28.4 r0 bottom value=10nF/50V/1005/K
C54 "C [1005]" C1005 139,26.2 r90 bottom value=10nF/50V/1005/K
C55 "C [1005]" C1005 142.4,28 r180 bottom value=10nF/50V/1005/K
C56 "C [1005]" C1005 140.2,26.2 r90 bottom value=10nF/50V/1005/K
C57 "C [1005]" C1005 139.6,32.4 r270 bottom value=10nF/50V/1005/K
C58 "C [1005]" C1005 138.2,32.4 r270 bottom value=10nF/50V/1005/K
C59 "C [1608]" C1608 144.2,37 r0 top value=0.1uF/50V/1608/K
C60 "C [1608]" C1608 144.2,38.8 r0 top value=0.1uF/50V/1608/K
C61 "C [1005]" C1005 141,32.4 r270 bottom value=10nF/50V/1005/K
C62 "C [1005]" C1005 137.2,25.8 r0 bottom value=10nF/50V/1005/K
C63 "C [1608]" C1608 148.2,41.2 r0 top value=1uF/50V/1608/K
C64 "C [2012]" C2012 148.2,36.2 r0 top value=10uF/50V/2012/K
C65 "C [1005]" C1005 115,20.6 r270 top value=27pF/50V/1005/K
C66 "C [1005]" C1005 115,23 r90 top value=27pF/50V/1005/K
C67 "C [2012]" C2012 118,48.6 r180 top value=10uF/50V/2012/K
C68 "C [2012]" C2012 123.4,48.6 r180 top value=10uF/50V/2012/K
C69 "C [3216]" C3216#1 99.6,28.2 r180 top value=100uF/10V/3216/K
C70 "C [3216]" C3216#1 99.6,30.8 r180 top value=47uF/16V/3216/M
C71 "C [3216]" C3216#1 118,36.4 r180 top value=100uF/10V/3216/K
C72 "C [3216]" C3216#1 118,33.8 r180 top value=47uF/16V/3216/M
C73 "C [3216]" C3216#1 123.4,36.4 r180 top value=100uF/10V/3216/K
C74 "C [3216]" C3216#1 123.4,33.8 r180 top value=47uF/16V/3216/M
C77 "C [2012]" C2012 144.2,40.8 r180 top value=10uF/50V/2012/K
C78 "C [1608]" C1608 141.3,37.8 r270 top value=0.1uF/50V/1608/K
C79 "C [1608]" C1608 138.6,22.2 r270 top value=0.1uF/50V/1608/K
C80 "C [1608]" C1608 139.5,37.8 r270 top value=0.1uF/50V/1608/K
C81 "C [1608]" C1608 136.8,22.2 r270 top value=0.1uF/50V/1608/K
C82 "C [1608]" C1608 135.2,37.2 r180 top value=1uF/50V/1608/K
C83 "C [1608]" C1608 144.6,22.2 r270 top value=0.1uF/50V/1608/K
C84 "C [1608]" C1608 142.8,22.2 r270 top value=0.1uF/50V/1608/K
C85 "C [1005]" C1005 133.4,24.8 r270 top value=27pF/50V/1005/K
C86 "C [1005]" C1005 133.4,27 r90 top value=27pF/50V/1005/K
C87 "C [1608]" C1608 128.8,37.9 r180 bottom value=0.1uF/50V/1608/K
C88 "C [1005]" C1005 11,27.8 r270 bottom value=1uF/50V/1005/K
C89 "C [1005]" C1005 12.2,27.8 r270 bottom value=0.1uF/50V/1005/K
C90 "C [1005]" C1005 11.6,22.2 r180 bottom value=1uF/50V/1005/K
C91 "C [1005]" C1005 11.6,23.6 r180 bottom value=0.1uF/50V/1005/K
C92 "C [1608]" C1608 7.2,35.2 r90 bottom value=0.1uF/50V/1608/K
C93 "C [1005]" C1005 11.6,30.4 r0 top value=NC/50V/1005/K
C94 "C [1005]" C1005 9.2,30.4 r180 top value=NC/50V/1005/K
C95 "C [1005]" C1005 11.8,43.8 r0 top value=27pF/50V/1005/K
C96 "C [1005]" C1005 9,43.8 r180 top value=27pF/50V/1005/K
C97 "C [1608]" C1608 19,35.2 r90 bottom value=0.1uF/50V/1608/K
C98 "C [1005]" C1005 23.4,30.4 r0 top value=NC/50V/1005/K
C99 "C [1005]" C1005 21,30.4 r180 top value=NC/50V/1005/K
C100 "C [1005]" C1005 23.6,43.8 r0 top value=27pF/50V/1005/K
C101 "C [1005]" C1005 20.8,43.8 r180 top value=27pF/50V/1005/K
C102 "C [1005]" C1005 22.8,27.8 r270 bottom value=1uF/50V/1005/K
C103 "C [1005]" C1005 24,27.8 r270 bottom value=0.1uF/50V/1005/K
C104 "C [1005]" C1005 23.4,23.6 r180 bottom value=1uF/50V/1005/K
C105 "C [1005]" C1005 23.4,22.2 r180 bottom value=0.1uF/50V/1005/K
C106 "C [1005]" C1005 30.2,30.68 r180 bottom value=1uF/50V/1005/K
C107 "C [1005]" C1005 30.2,31.8 r180 bottom value=0.1uF/50V/1005/K
C108 "C [1005]" C1005 32.8,25.4 r180 bottom value=1uF/50V/1005/K
C109 "C [1005]" C1005 32.8,24.2 r180 bottom value=0.1uF/50V/1005/K
C110 "C [1608]" C1608 34,34.2 r0 top value=NC/50V/1608/K
C111 "C [1608]" C1608 30.8,34.2 r180 top value=NC/50V/1608/K
C112 "C [1005]" C1005 40.4,30.6 r180 bottom value=1uF/50V/1005/K
C113 "C [1005]" C1005 40.4,31.8 r180 bottom value=0.1uF/50V/1005/K
C114 "C [1005]" C1005 42.8,25.4 r180 bottom value=1uF/50V/1005/K
C115 "C [1005]" C1005 42.8,24.2 r180 bottom value=0.1uF/50V/1005/K
C116 "C [1608]" C1608 44,34.2 r0 top value=NC/50V/1608/K
C117 "C [1608]" C1608 40.8,34.2 r180 top value=NC/50V/1608/K
CPU_RUN "LED Green[1608]" LED1608 99,81.8 r180 top value=GREEN
D1 "1N4148W-7-F" SOD-123 29,80.2 r270 top
D2 "B140-E3/61T" DO-214AC(SMA)_21 135.2,42 r90 top
DC1 "URB2405YMD-20WR3" URB2405YMD-20WR3 146.6,61.8 r180 top
DC2 "RI3-0505S" RI3-0505S 50.6,27.4 r90 top
FGND "TP" ST-1-1 164.6,34.8 r90 top value=Value
FL1 "SRF3225TP-501Y" SRF3225TP-501Y 156.4,20.4 r90 top
FL2 "YFF18SC1H472M" YFF18SC1H472M 10.4,12.8 r270 top value=4700pF
FL3 "DLW43SH110XK2L" DLW43SH110XK2L 9.4,17.8 r270 top
FL4 "YFF18SC1H472M" YFF18SC1H472M 8.4,12.8 r270 top value=4700pF
FL5 "YFF18SC1H472M" YFF18SC1H472M 22.2,12.8 r270 top value=4700pF
FL6 "DLW43SH110XK2L" DLW43SH110XK2L 21.2,17.8 r270 top
FL7 "YFF18SC1H472M" YFF18SC1H472M 20.2,12.8 r270 top value=4700pF
FL8 "YFF18SC1H472M" YFF18SC1H472M 30.4,12.8 r270 top value=4700pF
FL9 "DLW43SH110XK2L" DLW43SH110XK2L 31.4,19.8 r270 top
FL10 "YFF18SC1H472M" YFF18SC1H472M 32.4,12.8 r270 top value=4700pF
FL11 "YFF18SC1H472M" YFF18SC1H472M 40.6,12.8 r270 top value=4700pF
FL12 "DLW43SH110XK2L" DLW43SH110XK2L 41.6,19.8 r270 top
FL13 "YFF18SC1H472M" YFF18SC1H472M 42.6,12.8 r270 top value=4700pF
FL14 "SRF3225TP-501Y" SRF3225TP-501Y 11.8,69.2 r0 bottom
FL15 "SRF3225TP-501Y" SRF3225TP-501Y 100,24.8 r180 top
FL16 "SRF3225TP-501Y" SRF3225TP-501Y 118,40.4 r270 top
FL17 "SRF3225TP-501Y" SRF3225TP-501Y 123.4,40.4 r270 top
FUSE1 "MF-LSMF185/33X-2" MF-LSMF185_33X-2 155.2,29.6 r90 top
H1 "HOLE_(3/6)" NTH_3.6 4,4 r0 top
H2 "HOLE_(3/6)" NTH_3.6 166,18 r0 top
H3 "HOLE_(3/6)" NTH_3.6 4,86 r0 top
H4 "HOLE_(3/6)" NTH_3.6 166,86 r0 top
IC1 "DS3232MZ+" SOIC8_1.27_6.0 16.8,59 r0 top
IC2 "MAX22026FAWA+" SOIC8-1.27_7.9 31.4,28 r180 top
IC3 "MAX22026FAWA+" SOIC8-1.27_7.9 41.6,28 r180 top
J1 "EDSTL950/3" EDSTL950_3 154,9 r0 top
J2 "A1-10PA-2.54DSA(71)" A1-10PA-2.54DSA 38,77 r180 top
J3 "DF40HC(3.0)-100DS-0.4V" DF40HC(3.0)-100DS-0.4V 72,41 r0 top
J4 "A1-10PA-2.54DSA(71)" A1-10PA-2.54DSA 83,85 r180 top
J5 "503398-1892" MOLEX_503398-1892 7,74 r90 top
J6 "4728" 4728 124,85 r0 top
J7 "208658-1051" MOLEX_208658-1051 58,5 r0 top
J8 "47053-1000" 47053-1000 5,62.2 r90 top
J9 "HW-UAF-02" HW-UAF-02 97,12 r0 top
J10 "85793-1003" MOLEX_85793-1003 80,10 r270 top
J11 "HW-UAF-25" HW-UAF-25 116,14.6 r0 top
J12 "KJX-USB-AF-3201" KJX-USB-AF-3201 135,10.6 r0 top
J13 "MRT9P3.81SQ-04P" MRT9P3.81SQ-04P 18,7 r0 top
J14 "A2-2PA-2.54DSA" A2-2PA-2.54DSA 5.4,14 r180 top
J15 "A2-2PA-2.54DSA" A2-2PA-2.54DSA 17.2,14 r180 top
J16 "MRT9P3.81SQ-04P" MRT9P3.81SQ-04P 38,7 r0 top
J17 "A2-2PA-2.54DSA" A2-2PA-2.54DSA 36.2,14 r180 top
J18 "A2-2PA-2.54DSA" A2-2PA-2.54DSA 46.4,14 r180 top
L1 "BLM21PG121SN1D" L2012 163.4,49.8 r90 top
L2 "BLM21PG121SN1D" L2012 132.2,65.6 r270 top
L5 "BLM21PG121SN1D" L2012 112,48.4 r180 top
L6 "BLM21PG121SN1D" L2012 109,36.4 r270 top
L7 "BLM21PG121SN1D" L2012 56.4,24 r90 top
L8 "BLM21PG121SN1D" L2012 53,34.8 r180 top
L9 "BLM21PG121SN1D" L2012 140,40.8 r0 top
L10 "BLM21PG121SN1D" L2012 154,14.6 r90 top
L11 "BLM21PG121SN1D" L2012 159,14.6 r90 top
L12 "BLM21PG121SN1D" L2012 50.4,18.4 r0 bottom
LS1 "BMX-2705" BUZZER-BMX-2705 23,78.8 r90 top
PWR_ON "LED Green[1608]" LED1608 98.4,87 r0 top value=GREEN
Q1 "BSS138" SOT23L 29,84.8 r180 top
R1 "R [1608]_J" R1608 164.6,26.6 r90 top value=7.5k/1608/J
R2 "R [1608]_J" R1608 128,65.6 r90 top value=1k/1608/J
R3 "R [1608]_J" R1608 5.6,20.4 r90 top value=1k/1608/J
R4 "R [1608]_J" R1608 4.8,39.2 r270 top value=430/1608/J
R5 "R [2012]_J" R2012 113.6,42 r270 top value=1/2012/J
R6 "R [1608]_F" R1608 113.6,45.6 r90 top value=1K/1608/F
R7 "R [2012]_F" R2012 29,76 r270 top value=1K/2012/F
R8 "R [1608]_J" R1608 14.8,61 r270 bottom value=4.7k/1608/F
R9 "R [1608]_J" R1608 16.6,61 r270 bottom value=4.7k/1608/F
R10 "R [1005]_F" R1005 47.4,82.4 r90 top value=10k/1005/F
R11 "R [1608]_F" R1608 32.6,86 r0 top value=1K/1608/F
R12 "R [1608]_J" R1608 23,69.4 r90 top value=510k/1608/F
R13 "R [1608]_J" R1608 28.2,69.4 r90 top value=510k/1608/F
R14 "R [1608]_J" R1608 95.2,81.8 r0 top value=430/1608/F
R15 "R [1608]_J" R1608 99.8,84.4 r90 top value=430/1608/F
R16 "R [1005]_F" R1005 10.6,53.6 r180 top value=36k/1005/F
R17 "R [1005]_F" R1005 16,74 r180 top value=10k/1005/F
R21 "R [1608]_J" R1608 86.8,32.4 r0 bottom value=470/1608/F
R22 "R [1608]_J" R1608 74.8,32.4 r0 bottom value=470/1608/F
R28 "R [1608]_J" R1608 118,44.2 r0 bottom value=100k/1608/F
R29 "R [1608]_J" R1608 123.4,44.2 r0 bottom value=100k/1608/F
R30 "R [1608]_J" R1608 137.8,37.8 r270 top value=1.6k/1608/F
R31 "R [1608]_J" R1608 135,22.2 r90 top value=1.6k/1608/F
R32 "R [1608]_J" R1608 132,45 r270 top value=10k/1608/F
R33 "R [1608]_J" R1608 130.2,45 r270 top value=10k/1608/F
R34 "R [1608]_J" R1608 128.4,45 r270 top value=10k/1608/F
R35 "R [1608]_J" R1608 127.4,33.2 r90 top value=10k/1608/F
R36 "R [1608]_J" R1608 129.2,33.2 r90 top value=100k/1608/F
R37 "R [1608]_J" R1608 8.8,32.2 r0 top value=10k/1608/F
R38 "R [1608]_J" R1608 12,32.2 r180 top value=10k/1608/F
R39 "R [1608]_J" R1608 9.4,15.2 r0 bottom value=120/1608/J
R40 "R [1608]_J" R1608 20.6,32.2 r0 top value=10k/1608/F
R41 "R [1608]_J" R1608 23.8,32.2 r180 top value=10k/1608/F
R42 "R [1608]_J" R1608 21.2,15.2 r0 bottom value=120/1608/J
R43 "R [1608]_J" R1608 29.8,15.2 r180 top value=510/1608/J
R44 "R [1608]_J" R1608 30.8,36 r0 top value=10k/1608/F
R45 "R [1608]_J" R1608 34,36 r0 top value=10k/1608/F
R46 "R [1608]_J" R1608 33,15.2 r180 top value=510/1608/J
R47 "R [1608]_J" R1608 31.4,15.2 r180 bottom value=120/1608/J
R48 "R [1608]_J" R1608 40,15.2 r180 top value=510/1608/J
R49 "R [1608]_J" R1608 40.8,36 r0 top value=10k/1608/F
R50 "R [1608]_J" R1608 44,36 r0 top value=10k/1608/F
R51 "R [1608]_J" R1608 43.2,15.2 r180 top value=510/1608/J
R52 "R [1608]_J" R1608 41.6,15.2 r180 bottom value=120/1608/J
R53 "R [1608]_J" R1608 106,24.2 r180 bottom value=100k/1608/F
R54 "R [1608]_J" R1608 96.6,17.8 r270 bottom value=2.2k/1608/F
R55 "R [1608]_J" R1608 96.6,21 r270 bottom value=2.2k/1608/F
R56 "R [1608]_J" R1608 122.6,29 r270 top value=36k/1608/F
R57 "R [1608]_J" R1608 124.4,29 r270 top value=36k/1608/F
R58 "R [1608]_J" R1608 114.2,29 r270 top value=36k/1608/F
R59 "R [1608]_J" R1608 120.8,29 r270 top value=36k/1608/F
R60 "R [1608]_J" R1608 116,18.4 r0 top value=12k/1608/F
SW1 "TS-1187" TS-1187 40.6,83.8 r0 top
U1 "LT1764EFE-3.3#PBF" TSSOP16-0.65_6.5_EP 109.4,42.8 r0 top value=3.3V/3A
U2 "SN74LVC1G17DBVR" SOT23_5 31.2,69.4 r270 top
U3 "SN74LVC1G17DBVR" SOT23_5 33.4,81.8 r90 top
U4 "SN74LVC1G17DBVR" SOT23_5 96.6,84.4 r270 top
U5 "EMC2301-1-ACZL-TR" MSOP8_0.65_5.0 11.2,58 r180 top
U6 "RT9742GGJ5" SOT23_5 16.8,71.6 r90 top
U8 "RT9742SNGV" SOT23L 50.4,21.6 r180 bottom
U9 "ESD224" USON10_0.5_1.1X2.6 61.8,15 r90 top
U10 "ESD224" USON10_0.5_1.1X2.6 58.6,15 r90 top
U11 "TPD6E05U06" USON14_0.5_1.35X3.5 54.8,15 r90 top
U12 "LD57100J105R" WLCSP6_0.4P 148.2,38.8 r90 top
U13 "RT9742CGJ5" SOT23_5 118,45.4 r0 top
U14 "RT9742CGJ5" SOT23_5 123.4,45.4 r0 top
U15 "UPD720202K8-701-BAA-A" QFN48_0.5_7X7_EP 139.4,29.4 r270 top
U16 "AT25DN512C-SSHF-B" SOIC8_1.27_6.0 129.6,39 r180 top
U17 "ISO1044BD" SOIC8_1.27_6.0 10.4,25.2 r180 top
U18 "MCP2518FDT-H/SL" SOIC14_1.27_6.0 13,34.4 r90 top
U19 "ISO1044BD" SOIC8_1.27_6.0 22.2,25.2 r180 top
U20 "MCP2518FDT-H/SL" SOIC14_1.27_6.0 24.8,34.4 r90 top
U21 "RT9742CGJ5" SOT23_5 106,24.8 r270 top
U22 "TPD2EUSB30DRTR" SOT23L 100.6,16.6 r90 top
U23 "FSUSB42MUX" MSOP10_0.5_5.0 101.4,20.6 r270 top
U24 "USB2512B-I/M2" QFN36_0.5_6X6_EP 120.2,22.6 r90 top
Y1 "ECS-240-20-30B-TR" ECS-240-20-30B-TR 112,22.4 r90 top
Y2 "ECS-240-20-30B-TR" ECS-240-20-30B-TR 130.2,26.4 r90 top
Y3 "ECS-400-20-30B-DU-TR" ECS-400-20-30B-DU-TR 10.4,46.8 r180 top
Y4 "ECS-400-20-30B-DU-TR" ECS-400-20-30B-DU-TR 22.2,46.8 r180 top

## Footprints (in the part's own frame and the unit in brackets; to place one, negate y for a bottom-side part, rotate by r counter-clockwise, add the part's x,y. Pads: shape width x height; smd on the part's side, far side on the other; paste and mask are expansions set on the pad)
4728 [mm] "FFC_CONNECTOR"
  rect 0.5x1.5 smd: 1(-7,-1.65) 2(-6,-1.65) 3(-5,-1.65) 4(-4,-1.65) 5(-3,-1.65) 6(-2,-1.65) 7(-1,-1.65) 8(0,-1.65) 9(1,-1.65) 10(2,-1.65) 11(3,-1.65) 12(4,-1.65) 13(5,-1.65) 14(6,-1.65) 15(7,-1.65) 16(7,1.65) 17(6,1.65) 18(5,1.65) 19(4,1.65) 20(3,1.65) 21(2,1.65) 22(1,1.65) 23(0,1.65) 24(-1,1.65) 25(-2,1.65) 26(-3,1.65) 27(-4,1.65) 28(-5,1.65) 29(-6,1.65) 30(-7,1.65)
  silkscreen extent -11,-3.2 11,3.2, body extent -11,-2.25 11,2.25, height 5.4
47053-1000 [mm]
  rect 1.53x1.53 hole 1.02: 1(0,0)
  round 1.55 hole 1.02: 2(-2.54,0) 3(-5.08,0) 4(-7.62,0)
  round 0.65 hole 1.3 unplated: 5(-5.08,-2.16)
  silkscreen extent -9.19,-2.54 1.39,3.3, body extent -9,-2.54 1.2,3.3, height 7.5
A1-10PA-2.54DSA [mil]
  rrect50% 60x60 hole 39: 1(-200,-50)
  round 60 hole 39: 2(-200,50) 3(-100,-50) 4(-100,50) 5(0,-50) 6(0,50) 7(100,-50) 8(100,50) 9(200,-50) 10(200,50)
  silkscreen extent -250,-125 250,100, body extent -244,-100 244,100, height 340
A2-2PA-2.54DSA [mil]
  rect 60x60 hole 39.37: 1(0,-50)
  round 60 hole 39.37: 2(0,50)
  silkscreen extent -75,-100 50,100, body extent -57,-100 57,100, height 335
BUZZER-BMX-2705 [mm]
  rect 3x1.5 smd: N(4.5,0) P(-4.5,0)
  silkscreen extent -4.5,-4.6 4.5,6, body extent -4.6,-4.6 4.6,6, height 3.2
C1005 [mm] "Chip Capacitor, 2-Leads, Body 1.0x0.5mm, IPC Medium Density"
  rrect50% 0.54x0.64 smd: 1(-0.51,0) 2(0.51,0)
  silkscreen extent -0.95,-0.5 0.95,0.5, body extent -0.55,-0.28 0.55,0.27, height 0.35
C1608 [mm] "Chip Capacitor, 2-Leads, Body 1.6x0.8mm, IPC Medium Density"
  rrect50% 0.8x0.95 smd: 1(-0.825,0) 2(0.825,0)
  silkscreen extent -1.45,-0.75 1.45,0.75, body extent -0.85,-0.45 0.85,0.45, height 0.45
C2012 [mm] "Chip Capacitor, 2-Leads, Body 2.0x1.2mm, IPC Medium Density"
  rrect50% 1.025x1.4 smd: 1(-0.915,0) 2(0.915,0)
  silkscreen extent -1.65,-0.95 1.65,0.95, body extent -1.05,-0.63 1.05,0.63, height 0.5
C3216#1 [mm] "Chip Capacitor, 2-Leads, Body 3.2x1.6mm, IPC Medium Density"
  rrect50% 1.125x1.75 smd: 1(-1.465,0) 2(1.465,0)
  silkscreen extent -2.25,-1.15 2.25,1.15, body extent -1.65,-0.85 1.65,0.85, height 0.6
C3216#2 [mm] "1206"
  rect 1.397x1.651 smd mask+0: 1(-1.27,0) 2(1.27,0)
  silkscreen extent -2.16,-1.02 2.16,1.02, body extent -1.99,-0.8 2.01,0.8, height 1.53
CH291-1220LF [mm] "BATTERY-CR1220"
  round 1 hole 1 unplated mask+0: 0(-3.5,0)
  round 1.3 hole 1.3 unplated mask+0: 0(4,0)
  rect 3.6x2.6 smd mask+0: 1(8.2,0)
  rect 4.3x2.3 smd mask+0: 2(-7.6,0)
  silkscreen extent -7.35,-7.5 10.08,7.5, body extent -8.74,-7.5 9.76,7.49, height 3.94
DF40HC(3.0)-100DS-0.4V [mm]
  rect 0.2x0.7 smd: 1(9.8,35.54) 2(9.8,32.46) 3(9.4,35.54) 4(9.4,32.46) 5(9,35.54) 6(9,32.46) 7(8.6,35.54) 8(8.6,32.46) 9(8.2,35.54) 10(8.2,32.46) 11(7.8,35.54) 12(7.8,32.46) 13(7.4,35.54) 14(7.4,32.46) 15(7,35.54) 16(7,32.46) 17(6.6,35.54) 18(6.6,32.46) 19(6.2,35.54) 20(6.2,32.46) 21(5.8,35.54) 22(5.8,32.46) 23(5.4,35.54) 24(5.4,32.46) 25(5,35.54) 26(5,32.46) 27(4.6,35.54) 28(4.6,32.46) 29(4.2,35.54) 30(4.2,32.46) 31(3.8,35.54) 32(3.8,32.46) 33(3.4,35.54) 34(3.4,32.46) 35(3,35.54) 36(3,32.46) 37(2.6,35.54) 38(2.6,32.46) 39(2.2,35.54) 40(2.2,32.46) 41(1.8,35.54) 42(1.8,32.46) 43(1.4,35.54) 44(1.4,32.46) 45(1,35.54) 46(1,32.46) 47(0.6,35.54) 48(0.6,32.46) 49(0.2,35.54) 50(0.2,32.46) 51(-0.2,35.54) 52(-0.2,32.46) 53(-0.6,35.54) 54(-0.6,32.46) 55(-1,35.54) 56(-1,32.46) 57(-1.4,35.54) 58(-1.4,32.46) 59(-1.8,35.54) 60(-1.8,32.46) 61(-2.2,35.54) 62(-2.2,32.46) 63(-2.6,35.54) 64(-2.6,32.46) 65(-3,35.54) 66(-3,32.46) 67(-3.4,35.54) 68(-3.4,32.46) 69(-3.8,35.54) 70(-3.8,32.46) 71(-4.2,35.54) 72(-4.2,32.46) 73(-4.6,35.54) 74(-4.6,32.46) 75(-5,35.54) 76(-5,32.46) 77(-5.4,35.54) 78(-5.4,32.46) 79(-5.8,35.54) 80(-5.8,32.46) 81(-6.2,35.54) 82(-6.2,32.46) 83(-6.6,35.54) 84(-6.6,32.46) 85(-7,35.54) 86(-7,32.46) 87(-7.4,35.54) 88(-7.4,32.46) 89(-7.8,35.54) 90(-7.8,32.46) 91(-8.2,35.54) 92(-8.2,32.46) 93(-8.6,35.54) 94(-8.6,32.46) 95(-9,35.54) 96(-9,32.46) 97(-9.4,35.54) 98(-9.4,32.46) 99(-9.8,35.54) 100(-9.8,32.46) 101(9.8,1.54) 102(9.8,-1.54) 103(9.4,1.54) 104(9.4,-1.54) 105(9,1.54) 106(9,-1.54) 107(8.6,1.54) 108(8.6,-1.54) 109(8.2,1.54) 110(8.2,-1.54) 111(7.8,1.54) 112(7.8,-1.54) 113(7.4,1.54) 114(7.4,-1.54) 115(7,1.54) 116(7,-1.54) 117(6.6,1.54) 118(6.6,-1.54) 119(6.2,1.54) 120(6.2,-1.54) 121(5.8,1.54) 122(5.8,-1.54) 123(5.4,1.54) 124(5.4,-1.54) 125(5,1.54) 126(5,-1.54) 127(4.6,1.54) 128(4.6,-1.54) 129(4.2,1.54) 130(4.2,-1.54) 131(3.8,1.54) 132(3.8,-1.54) 133(3.4,1.54) 134(3.4,-1.54) 135(3,1.54) 136(3,-1.54) 137(2.6,1.54) 138(2.6,-1.54) 139(2.2,1.54) 140(2.2,-1.54) 141(1.8,1.54) 142(1.8,-1.54) 143(1.4,1.54) 144(1.4,-1.54) 145(1,1.54) 146(1,-1.54) 147(0.6,1.54) 148(0.6,-1.54) 149(0.2,1.54) 150(0.2,-1.54) 151(-0.2,1.54) 152(-0.2,-1.54) 153(-0.6,1.54) 154(-0.6,-1.54) 155(-1,1.54) 156(-1,-1.54) 157(-1.4,1.54) 158(-1.4,-1.54) 159(-1.8,1.54) 160(-1.8,-1.54) 161(-2.2,1.54) 162(-2.2,-1.54) 163(-2.6,1.54) 164(-2.6,-1.54) 165(-3,1.54) 166(-3,-1.54) 167(-3.4,1.54) 168(-3.4,-1.54) 169(-3.8,1.54) 170(-3.8,-1.54) 171(-4.2,1.54) 172(-4.2,-1.54) 173(-4.6,1.54) 174(-4.6,-1.54) 175(-5,1.54) 176(-5,-1.54) 177(-5.4,1.54) 178(-5.4,-1.54) 179(-5.8,1.54) 180(-5.8,-1.54) 181(-6.2,1.54) 182(-6.2,-1.54) 183(-6.6,1.54) 184(-6.6,-1.54) 185(-7,1.54) 186(-7,-1.54) 187(-7.4,1.54) 188(-7.4,-1.54) 189(-7.8,1.54) 190(-7.8,-1.54) 191(-8.2,1.54) 192(-8.2,-1.54) 193(-8.6,1.54) 194(-8.6,-1.54) 195(-9,1.54) 196(-9,-1.54) 197(-9.4,1.54) 198(-9.4,-1.54) 199(-9.8,1.54) 200(-9.8,-1.54)
  round 5.2 hole 2.5: ""(-21.5,33.5) ""(-21.5,0.5) ""(26.5,0.5) ""(26.5,33.5)
  silkscreen extent -25,-3 30,37, body extent -11.3,-1.87 11.3,35.87, height 3.15
DLW43SH110XK2L [mm]
  rect 1.45x0.9 smd: 1(-2.225,-1.25) 2(2.225,-1.25) 3(2.225,1.25) 4(-2.225,1.25)
  silkscreen extent -2.7,-2.3 2.35,1.7
DO-214AC(SMA)_21 [mm]
  rect 2x2 smd: 1(2.1,0) 2(-2.1,0)
  silkscreen extent -2.3,-1.4 2.3,1.4, body extent -2.74,-1.4 2.74,1.4, height 2.24
ECS-240-20-30B-TR [mm]
  rect 2x1.4 smd: 1(-2.2,-1.2) 2(2.2,-1.2) 3(2.2,1.2) 4(-2.2,1.2)
  silkscreen extent -2.75,-2.5 2.5,1.6, body extent -2.5,-1.6 2.5,1.6, height 0.85
ECS-400-20-30B-DU-TR [mm]
  rect 2x1.4 smd: 1(-2.2,-1.2) 2(2.2,-1.2) 3(2.2,1.2) 4(-2.2,1.2)
  silkscreen extent -2.75,-2.5 2.5,1.6, body extent -2.5,-1.6 2.5,1.6, height 0.85
EDSTL950_3 [mm]
  rect 2.4x2.4 hole 1.7: 1(0,0)
  round 2.4 hole 1.7: 2(5.08,0) 3(10.16,0)
  silkscreen extent -3.18,-10 13.34,2.9, body extent -3.18,-10 13.37,2, height 8.4
HW-UAF-02 [mm]
  rect 1.524x1.524 hole 0.92: 1(0,0)
  round 1.524 hole 0.92: 2(2.5,0) 3(4.5,0) 4(7,0)
  round 3.5 hole 2.3: 5(-3.07,-2.71) 6(10.07,-2.71)
  silkscreen extent -3.86,-13.01 10.86,2, body extent -3.86,-13.01 10.86,1.12, height 7
HW-UAF-25 [mm]
  rect 1.5x1.5 hole 0.92: 1(0,-2.7)
  round 1.5 hole 0.92: 2(2.5,-2.7) 3(4.5,-2.7) 4(7,-2.7) 5(0,0) 6(2.5,0) 7(4.5,0) 8(7,0)
  round 3 hole 2.3: 9(-3.07,0.27) 10(10.07,0.27) 11(-3.07,-5.41) 12(10.07,-5.41)
  silkscreen extent -3.81,-15.71 10.81,1.92, body extent -3.81,-15.71 10.81,1.42, height 15.6
KJX-USB-AF-3201 [mm]
  rect 1.2x1.2 hole 0.7: 1(0,0)
  round 1.2 hole 0.7: 2(2.5,0) 3(4.5,0) 4(7,0) 5(7.5,1.5) 6(5.5,1.5) 7(3.5,1.5) 8(1.5,1.5) 9(-0.5,1.5) 10(0,3.2) 11(2.5,3.2) 12(4.5,3.2) 13(7,3.2) 14(7.5,4.7) 15(5.5,4.7) 16(3.5,4.7) 17(1.5,4.7) 18(-0.5,4.7)
  round 3.5 hole 2.3: 19(-3.07,3.68) 20(10.07,3.68) 21(-3.07,-2) 22(10.07,-2)
  silkscreen extent -5,-11.64 10.75,6.02, body extent -3.8,-11.7 10.8,6, height 16.4
L2012 [mm] "Chip Inductor, 2-Leads, Body 2.0x1.2mm, IPC Medium Density"
  rrect50% 0.875x1.2 smd: 1(-1.062,0) 2(1.062,0)
  silkscreen extent -1.75,-0.85 1.75,0.85, body extent -1.05,-0.63 1.05,0.63, height 0.5
LED1608 [mm]
  rect 1x1 smd: 1(-0.9,0) 2(0.9,0)
  TOP pour cut-out: -0.4,0.8 0.4,0.8 0.4,-0.8 -0.4,-0.8
  silkscreen extent -1.5,-0.6 1.8,0.6, body extent -0.82,-0.36 0.83,0.37, height 0.68
MF-LSMF185_33X-2 [mm]
  rect 2x5.3 smd: 1(-3.705,0) 2(3.705,0)
  silkscreen extent -4.9,-2.8 4.9,2.8
MOLEX_85793-1003 [mm]
  round 1.4 hole 0.9: 1(-15.24,5.075) 2(-15.24,3.045) 3(-15.24,1.015) 4(-15.24,-1.015) 5(-15.24,-3.045) 6(-15.24,-5.075) 7(-17.78,6.095) 8(-17.78,4.065) 9(-17.78,2.035) 10(-17.78,-2.035) 11(-17.78,-4.065) 12(-17.78,-6.095) 13(-20.32,6.095) 14(-20.32,3.555) 15(-20.32,-3.555) 16(-20.32,-6.095)
  round 2.2 hole 1.6: 17(3.18,8.065) 18(3.18,-8.065)
  round 3.2 hole 3.2: ""(0,6.35) ""(0,-6.35)
  silkscreen extent -22,-9.6 11.1,10.71, body extent -21.96,-9.59 11.05,9.59, height 14.98
MOLEX_208658-1051 [mm]
  rect 0.3x2.6 smd: 1(4.5,5.235) 2(4,5.235) 3(3.5,5.235) 4(3,5.235) 5(2.5,5.235) 6(2,5.235) 7(1.5,5.235) 8(1,5.235) 9(0.5,5.235) 10(0,5.235) 11(-0.5,5.235) 12(-1,5.235) 13(-1.5,5.235) 14(-2,5.235) 15(-2.5,5.235) 16(-3,5.235) 17(-3.5,5.235) 18(-4,5.235) 19(-4.5,5.235)
  round 4.275 hole 2.85: 20(-7.25,4.475) 21(7.25,4.475)
  round 2.88 hole 1.92: 22(-7.25,-1.485) 23(7.25,-1.485)
  silkscreen extent -7.5,-6.07 7.5,7.2, body extent -8.57,-6.07 8.57,6.51, height 6.54
MOLEX_503398-1892 [mm]
  rect 0.7x1.1 smd: 1(-2.38,5.625) 2(-1.28,5.625) 3(-0.18,5.625) 4(0.92,5.625) 5(2.02,5.625) 6(3.12,5.625) 7(4.22,5.625) 8(5.32,5.625)
  rect 0.9x0.93 smd: 9(-4.17,-6.84)
  rect 1.05x0.78 smd: 10(0.095,-6.915)
  rect 1.14x1.83 smd: P1(-6.26,5.61)
  rect 0.86x2.8 smd: P2(6.4,5.125)
  rect 0.7x3.33 smd: P3(-6.48,-5.64) P4(6.48,-5.64)
  TOP keep-out region: -4.685,-6.738 -5.245,-6.738 -5.245,-4.575 -4.685,-4.575
  TOP keep-out region: -2.67,-6.93 -3.223,-6.93 -3.223,-6.375 -2.67,-6.375
  TOP keep-out region: -6.13,-1.276 -6.836,-1.276 -6.836,1.125 -6.13,1.125
  TOP keep-out region: 6.83,-3.975 6.13,-3.975 6.13,-6.525 -0.43,-6.525 -0.43,-7.305 -1.73,-7.305 -1.73,-5.125 0.57,-5.125 0.57,-3.875 -3.82,-3.875 -3.82,-1.275 -3.17,-1.275 -3.17,3.725 6.83,3.725
  silkscreen extent -6.55,-7.02 6.55,7.57, body extent -6.55,-7.02 6.55,7.04, height 1.4
MRT9P3.81SQ-04P [mm]
  rect 2x2 hole 1.4: 1(-5.715,0)
  round 2 hole 1.4: 2(-1.905,0) 3(1.905,0) 4(5.715,0)
  silkscreen extent -8.31,-8 8.31,2.1, body extent -8.3,-8 8.3,1.2, height 7.25
MSOP8_0.65_5.0 [mm]
  rect 0.305x2.032 smd: 1(-0.975,-2.15) 2(-0.325,-2.15) 3(0.325,-2.15) 4(0.975,-2.15) 5(0.975,2.15) 6(0.325,2.15) 7(-0.325,2.15) 8(-0.975,2.15)
  silkscreen extent -1.51,-3.62 1.5,0.88, body extent -1.5,-2.5 1.5,2.5, height 0.92
MSOP10_0.5_5.0 [mm]
  rect 0.27x1.5 smd: 1(-1,-2.2) 2(-0.5,-2.2) 3(0,-2.2) 4(0.5,-2.2) 5(1,-2.2) 6(1,2.2) 7(0.5,2.2) 8(0,2.2) 9(-0.5,2.2) 10(-1,2.2)
  silkscreen extent -1.5,-3.55 1.5,1.25, body extent -1.5,-2.51 1.5,2.51, height 1.05
NTH_3.6 [mm]
  round 3.6 hole 3.6: 1(0,0)
  Multi-Layer pour cut-out: 4,0 4,0.262 3.932,0.782 3.796,1.289 3.595,1.773 3.333,2.227 3.014,2.643 2.643,3.014 2.227,3.333 1.773,3.595 1.289,3.796 0.782,3.932 0.262,4 0,4 0,4 -0.262,4 -0.782,3.932 -1.289,3.796 -1.773,3.595 -2.227,3.333 -2.643,3.014 -3.014,2.643 -3.333,2.227 -3.595,1.773 -3.796,1.289 -3.932,0.782 -4,0.262 -4,0 -4,-0.262 -3.932,-0.782 -3.796,-1.289 -3.595,-1.773 -3.333,-2.227 -3.014,-2.643 -2.643,-3.014 -2.227,-3.333 -1.773,-3.595 -1.289,-3.796 -0.782,-3.932 -0.262,-4 0,-4 0.262,-4 0.782,-3.932 1.289,-3.796 1.773,-3.595 2.227,-3.333 2.643,-3.014 3.014,-2.643 3.333,-2.227 3.595,-1.773 3.796,-1.289 3.932,-0.782 4,-0.262 4,0
  silkscreen extent -4,-4 4,4
QFN36_0.5_6X6_EP [mm]
  rect 1.1x0.3 smd: 1(-2.9,2) 2(-2.9,1.5) 3(-2.9,1) 4(-2.9,0.5) 5(-2.9,0) 6(-2.9,-0.5) 7(-2.9,-1) 8(-2.9,-1.5) 9(-2.9,-2) 19(2.9,-2) 20(2.9,-1.5) 21(2.9,-1) 22(2.9,-0.5) 23(2.9,0) 24(2.9,0.5) 25(2.9,1) 26(2.9,1.5) 27(2.9,2)
  rect 0.3x1.1 smd: 10(-2,-2.9) 11(-1.5,-2.9) 12(-1,-2.9) 13(-0.5,-2.9) 14(0,-2.9) 15(0.5,-2.9) 16(1,-2.9) 17(1.5,-2.9) 18(2,-2.9) 28(2,2.9) 29(1.5,2.9) 30(1,2.9) 31(0.5,2.9) 32(0,2.9) 33(-0.5,2.9) 34(-1,2.9) 35(-1.5,2.9) 36(-2,2.9)
  rect 3.8x3.8 smd: 37(0,0)
  silkscreen extent -3.75,1.75 -3.5,2.25, body extent -3.05,-3.05 3.05,3.05, height 2
QFN48_0.5_7X7_EP [mm]
  rect 0.85x0.3 smd: 1(-3.45,2.75) 2(-3.45,2.25) 3(-3.45,1.75) 4(-3.45,1.25) 5(-3.45,0.75) 6(-3.45,0.25) 7(-3.45,-0.25) 8(-3.45,-0.75) 9(-3.45,-1.25) 10(-3.45,-1.75) 11(-3.45,-2.25) 12(-3.45,-2.75) 25(3.45,-2.75) 26(3.45,-2.25) 27(3.45,-1.75) 28(3.45,-1.25) 29(3.45,-0.75) 30(3.45,-0.25) 31(3.45,0.25) 32(3.45,0.75) 33(3.45,1.25) 34(3.45,1.75) 35(3.45,2.25) 36(3.45,2.75)
  rect 0.3x0.85 smd: 13(-2.75,-3.45) 14(-2.25,-3.45) 15(-1.75,-3.45) 16(-1.25,-3.45) 17(-0.75,-3.45) 18(-0.25,-3.45) 19(0.25,-3.45) 20(0.75,-3.45) 21(1.25,-3.45) 22(1.75,-3.45) 23(2.25,-3.45) 24(2.75,-3.45) 37(2.75,3.45) 38(2.25,3.45) 39(1.75,3.45) 40(1.25,3.45) 41(0.75,3.45) 42(0.25,3.45) 43(-0.25,3.45) 44(-0.75,3.45) 45(-1.25,3.45) 46(-1.75,3.45) 47(-2.25,3.45) 48(-2.75,3.45)
  rect 5.7x5.7 smd: 49(0,0)
  silkscreen extent -4.5,-4 4,4, body extent -3.55,-3.55 3.55,3.55, height 0.9
R1005 [mm] "Chip Resistor, 2-Leads, Body 1.00x0.50mm, IPC Medium Density"
  rrect50% 0.54x0.64 smd: 1(-0.51,0) 2(0.51,0)
  silkscreen extent -0.95,-0.5 0.95,0.5, body extent -0.55,-0.28 0.55,0.27, height 0.35
R1608 [mm] "Chip Resistor, 2-Leads, Body 1.60x0.80mm, IPC Medium Density"
  rrect50% 0.8x0.95 smd: 1(-0.825,0) 2(0.825,0)
  silkscreen extent -1.45,-0.75 1.45,0.75, body extent -0.85,-0.45 0.85,0.45, height 0.45
R2012 [mm] "Chip Resistor, 2-Leads, Body 2.00x1.20mm, IPC Medium Density"
  rrect50% 1.025x1.4 smd: 1(-0.915,0) 2(0.915,0)
  silkscreen extent -1.65,-0.95 1.65,0.95, body extent -1.05,-0.63 1.05,0.63, height 0.5
RI3-0505S [mm]
  rect 1.508x1.508 hole 1: 1(-3.75,-2.54)
  round 1.508 hole 1: 2(-1.21,-2.54) 3(1.33,-2.54) 4(3.87,-2.54)
  silkscreen extent -6.9,-4.5 5.75,3.8, body extent -5.75,-3 5.75,3, height 9.5
SOD-123 [mm]
  rect 0.91x1.22 smd: 1(1.635,0) 2(-1.635,0)
  silkscreen extent -1.49,-0.9 1.51,0.9, body extent -1.95,-0.9 1.95,0.9, height 1.18
SOIC8-1.27_7.9 [mm]
  rect 0.6x1.6 smd: 1(-1.905,-3.6) 2(-0.635,-3.6) 3(0.635,-3.6) 4(1.905,-3.6) 5(1.905,3.6) 6(0.635,3.6) 7(-0.635,3.6) 8(-1.905,3.6)
  TOP pour cut-out: -2.5,4.7 -2.5,2.6 2.5,2.6 2.5,4.7
  TOP pour cut-out: -2.5,-2.6 -2.5,-4.7 2.5,-4.7 2.5,-2.6
  silkscreen extent -2.5,-5.05 2.5,2.7
SOIC8_1.27_6.0 [mm]
  rect 0.6x1.5 smd: 1(-1.905,-2.75) 2(-0.635,-2.75) 3(0.635,-2.75) 4(1.905,-2.75) 5(1.905,2.75) 6(0.635,2.75) 7(-0.635,2.75) 8(-1.905,2.75)
  TOP pour cut-out: -2.5,-1.7 -2.5,-3.8 2.5,-3.8 2.5,-1.7
  TOP pour cut-out: -2.5,3.8 -2.5,1.7 2.5,1.7 2.5,3.8
  silkscreen extent -2.5,-4.2 2.5,1.8, body extent -2.45,-3 2.45,3, height 1.7
SOIC14_1.27_6.0 [mm]
  rect 0.55x2.2 smd: 1(0,0) 2(1.27,0) 3(2.54,0) 4(3.81,0) 5(5.08,0) 6(6.35,0) 7(7.62,0) 8(7.62,5.2) 9(6.35,5.2) 10(5.08,5.2) 11(3.81,5.2) 12(2.54,5.2) 13(1.27,5.2) 14(0,5.2)
  silkscreen extent -0.57,-1.8 8.19,3.7, body extent -0.57,-0.4 8.18,5.6, height 1.75
SOT23_5 [mil]
  rect 20x40 smd: 1(-37.4,-50) 2(0,-50) 3(37.4,-50) 4(37.4,50) 5(-37.4,50)
  silkscreen extent -79,-63 55,25, body extent -57,-55 57,55, height 57
SOT23L [mm]
  rect 1x1 smd mask+0.05: 1(-0.95,-1.3) 2(0.95,-1.3) 3(0,1.3)
  silkscreen extent -1.6,-2.85 1.6,1, body extent -1.5,-1.25 1.5,1.25, height 1.15
SRF3225TP-501Y [mm]
  rect 1.05x1.35 smd: 1(-1.675,-1.075) 2(1.675,-1.075) 3(1.675,1.075) 4(-1.675,1.075)
  silkscreen extent -2.1,-2.3 1.6,1.25, body extent -1.6,-1.25 1.6,1.25, height 2.2
ST-1-1 [mm]
  round 1.7 hole 1: 1(0,0)
  silkscreen extent -1.27,-1.27 1.27,1.27
TS-1187 [mm]
  rect 1.8x1.1 smd: 1(-3.1,1.85) 2(3.1,1.85) 3(-3.1,-1.85) 4(3.1,-1.85)
  silkscreen extent -2.6,-2.6 2.6,2.6, body extent -3.2,-2.6 3.2,2.6, height 1.5
TSSOP16-0.65_6.5_EP [mm]
  rect 0.3x1.5 smd: 1(-2.275,-2.95) 2(-1.625,-2.95) 3(-0.975,-2.95) 4(-0.325,-2.95) 5(0.325,-2.95) 6(0.975,-2.95) 7(1.625,-2.95) 8(2.275,-2.95) 9(2.275,2.95) 10(1.625,2.95) 11(0.975,2.95) 12(0.325,2.95) 13(-0.325,2.95) 14(-0.975,2.95) 15(-1.625,2.95) 16(-2.275,2.95)
  rect 3.58x2.94 smd: 17(0,0)
  TOP pour cut-out: -2.7,-1.4 -2.7,-4 2.7,-4 2.7,-1.4
  TOP pour cut-out: -2.7,4 -2.7,1.4 2.7,1.4 2.7,4
  silkscreen extent -2.68,-4.6 2.5,2, body extent -2.55,-3.25 2.55,3.25, height 1.2
URB2405YMD-20WR3 [mm]
  round 2.5 hole 1.5: 1(-10.16,10.16) 2(-10.16,2.54) 3(-10.16,-2.54) 4(10.16,-10.16) 5(10.16,0) 6(10.16,10.16)
  silkscreen extent -13.75,-12.7 12.7,12.7, body extent -12.7,-12.7 12.7,12.7, height 11.7
USON10_0.5_1.1X2.6 [mm]
  rect 0.565x0.2 smd: 1(-0.417,1) 2(-0.417,0.5) 4(-0.417,-0.5) 5(-0.417,-1) 6(0.417,-1) 7(0.417,-0.5) 9(0.417,0.5) 10(0.417,1)
  rect 0.565x0.4 smd: 3(-0.417,0) 8(0.417,0)
  silkscreen extent -1.2,-1.3 0.55,1.3
USON14_0.5_1.35X3.5 [mm]
  rect 0.75x0.25 smd: 1(-0.65,1.5) 2(-0.65,1) 3(-0.65,0.5) 4(-0.65,0) 5(-0.65,-0.5) 6(-0.65,-1) 7(-0.65,-1.5) 8(0.65,-1.5) 9(0.65,-1) 10(0.65,-0.5) 11(0.65,0) 12(0.65,0.5) 13(0.65,1) 14(0.65,1.5)
  silkscreen extent -1.5,-1.75 0.67,1.8
WLCSP6_0.4P [mm]
  round 0.25 smd mask+0.05: A1(-0.2,0.4) A2(0.2,0.4) B1(-0.2,0) B2(0.2,0) C1(-0.2,-0.4) C2(0.2,-0.4)
  silkscreen extent -0.77,-0.87 0.67,0.97
YFF18SC1H472M [mm]
  rect 0.6x0.8 smd mask+0.05: 1(-0.8,0) 3(0.8,0)
  rect 0.4x0.4 smd mask+0.05: 2(0,-0.4) 4(0,0.4)
  silkscreen extent -1.3,-0.8 1.3,0.8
